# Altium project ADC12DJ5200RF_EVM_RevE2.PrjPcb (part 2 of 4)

## Sheet Clocks2_RevE2.SchDoc: EVM REF CLK
size 431 x 279 mm; Date: Not shown in title block; ApprovedBy: Not shown in title block; CheckedBy: Not shown in title block; Author: Not shown in title block; CompanyName: Not shown in title block; DrawnBy: DWG; Engineer: DWG; Organization: Not shown in title block; Address1: Not shown in title block; Address2: Not shown in title block; Address3: Not shown in title block; Address4: Not shown in title block; DocumentNumber: 6; Revision: Use project parameter SCH_Rev; SheetNumber: 6; SheetTotal: 15; PageSetup: Record=PageOptions¦CenterHorizontal=True¦CenterVertical=True¦PrintScale=1.00¦XCorrection=1.00¦YCorrection=1.00¦PrintKind=0¦BorderSize=5000000¦LeftOffset=0¦BottomOffset=0¦Orientation=2¦PaperLength=1000¦PaperWidth=1000¦Scale=100¦PaperSource=15¦PrintQuality=600¦MediaType=1¦DitherType=10¦PaperKind=Letter¦PrintScaleMode=1
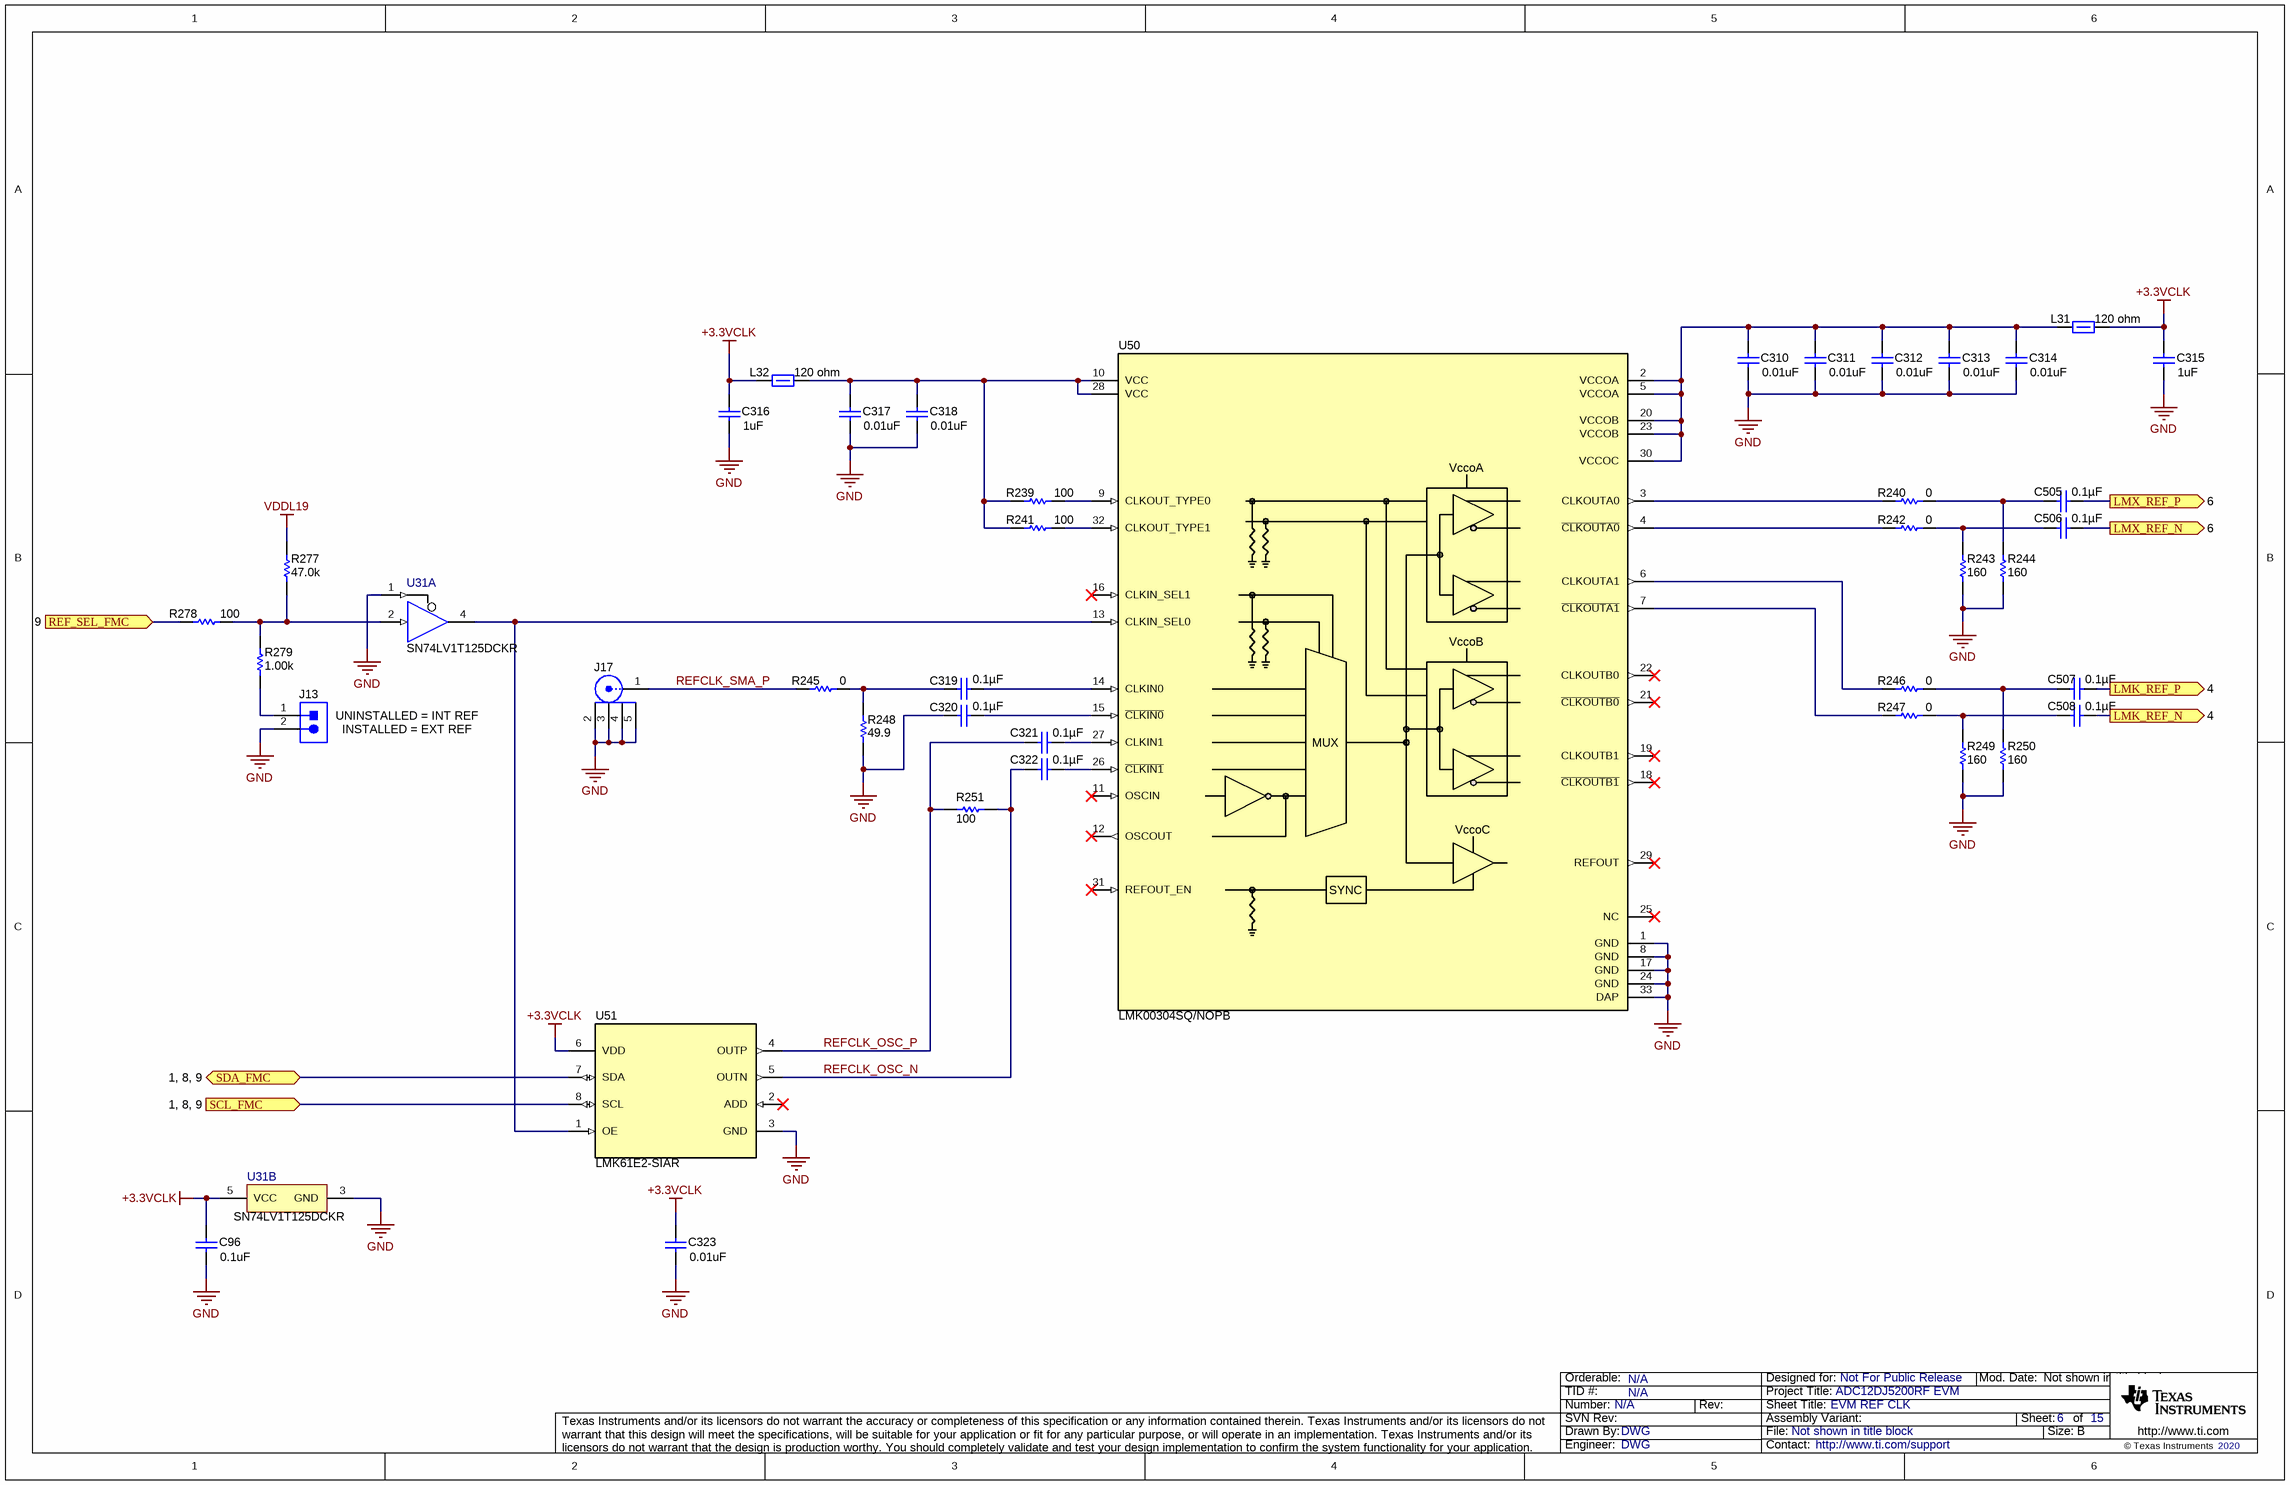
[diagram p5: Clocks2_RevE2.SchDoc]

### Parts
C96  ValueDisplayed: 0.1uF  [0201L]  (hidden comment: GRM033Z71C104KE14D)
C310  ValueDisplayed: 0.01uF  [0201L]  (hidden comment: GRM033R71A103KA01D)
C311  ValueDisplayed: 0.01uF  [0201L]  (hidden comment: GRM033R71A103KA01D)
C312  ValueDisplayed: 0.01uF  [0201L]  (hidden comment: GRM033R71A103KA01D)
C313  ValueDisplayed: 0.01uF  [0201L]  (hidden comment: GRM033R71A103KA01D)
C314  ValueDisplayed: 0.01uF  [0201L]  (hidden comment: GRM033R71A103KA01D)
C315  ValueDisplayed: 1uF  [0402L]  (hidden comment: GRM155R70J105KA12D)
C316  ValueDisplayed: 1uF  [0402L]  (hidden comment: GRM155R70J105KA12D)
C317  ValueDisplayed: 0.01uF  [0201L]  (hidden comment: GRM033R71A103KA01D)
C318  ValueDisplayed: 0.01uF  [0201L]  (hidden comment: GRM033R71A103KA01D)
C319  ValueDisplayed: 0.1µF  [0201_033L]  (hidden comment: 0201BB104KW160)
C320  ValueDisplayed: 0.1µF  [0201_033L]  (hidden comment: 0201BB104KW160)
C321  ValueDisplayed: 0.1µF  [0201_033L]  (hidden comment: 0201BB104KW160)
C322  ValueDisplayed: 0.1µF  [0201_033L]  (hidden comment: 0201BB104KW160)
C323  ValueDisplayed: 0.01uF  [0201L]  (hidden comment: GRM033R71A103KA01D)
C505  ValueDisplayed: 0.1µF  [0201_033L]  (hidden comment: 0201BB104KW160)
C506  ValueDisplayed: 0.1µF  [0201_033L]  (hidden comment: 0201BB104KW160)
C507  ValueDisplayed: 0.1µF  [0201_033L]  (hidden comment: 0201BB104KW160)
C508  ValueDisplayed: 0.1µF  [0201_033L]  (hidden comment: 0201BB104KW160)
J13  5-146261-1  [CONN_5-146261-1]  (value not drawn)
J17  SASF546-P26-X1  [CONN_LTI_SASF546-P26-X1]  (value not drawn)
L31  ValueDisplayed: 120 ohm  [0402L]  (hidden comment: 74279271)
L32  ValueDisplayed: 120 ohm  [0402L]  (hidden comment: 74279271)
R239  ValueDisplayed: 100  [0201L]  (hidden comment: RC0201FS-7D100RL)
R240  ValueDisplayed: 0  [0201L]  (hidden comment: CRCW02010000Z0ED)
R241  ValueDisplayed: 100  [0201L]  (hidden comment: RC0201FS-7D100RL)
R242  ValueDisplayed: 0  [0201L]  (hidden comment: CRCW02010000Z0ED)
R243  ValueDisplayed: 160  [0201L]  (hidden comment: RC0201FR-07160RL)
R244  ValueDisplayed: 160  [0201L]  (hidden comment: RC0201FR-07160RL)
R245  ValueDisplayed: 0  [0201L]  (hidden comment: CRCW02010000Z0ED)
R246  ValueDisplayed: 0  [0201L]  (hidden comment: CRCW02010000Z0ED)
R247  ValueDisplayed: 0  [0201L]  (hidden comment: CRCW02010000Z0ED)
R248  ValueDisplayed: 49.9  [0402L]  (hidden comment: ERJ-2RKF49R9X)
R249  ValueDisplayed: 160  [0201L]  (hidden comment: RC0201FR-07160RL)
R250  ValueDisplayed: 160  [0201L]  (hidden comment: RC0201FR-07160RL)
R251  ValueDisplayed: 100  [0201L]  (hidden comment: RC0201FS-7D100RL)
R277  ValueDisplayed: 47.0k  [0201L]  (hidden comment: RC0201FR-7D47KL)
R278  ValueDisplayed: 100  [0201L]  (hidden comment: RC0201FS-7D100RL)
R279  ValueDisplayed: 1.00k  [0201L]  (hidden comment: RC0201FS-7D1KL)
U31  SN74LV1T125DCKR  [DCK0005A_N]  (parts A,B of 2)
U50  LMK00304SQ/NOPB  [RTV0032A]
U51  LMK61E2-SIAR  [SIA0008B]

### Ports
LMK_REF_N (out, see 4), LMK_REF_P (out, see 4), LMX_REF_N (out, see 6), LMX_REF_P (out, see 6), REF_SEL_FMC (in, see 9), SCL_FMC (in, see 1, 8, 9), SDA_FMC (bidir, see 1, 8, 9)

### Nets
+3.3VCLK: C96.1 C315.1 C316.1 C323.1 L31.2 L32.1 U31.5(VCC) U51.6(VDD)
GND: C96.2 C310.2 C311.2 C312.2 C313.2 C314.2 C315.2 C316.2 C317.2 C318.2 C320.2 C323.2 J13.2 J17.2 J17.3 J17.4 J17.5 R243.1 R244.1 R248.1 R249.1 R250.1 U31.1(~{OE}) U31.3(GND) U50.1(GND) U50.8(GND) U50.17(GND) U50.24(GND) U50.33(DAP) U51.3(GND)
VDDL19: R277.2
LMK_REF_N: C508.1 ; port LMK_REF_N
LMK_REF_P: C507.1 ; port LMK_REF_P
LMX_REF_N: C506.1 ; port LMX_REF_N
LMX_REF_P: C505.1 ; port LMX_REF_P
REF_SEL_FMC: R278.2 ; port REF_SEL_FMC
REFCLK_OSC_N: C322.2 R251.1 U51.5(OUTN)
REFCLK_OSC_P: C321.2 R251.2 U51.4(OUTP)
REFCLK_SMA_P: J17.1 R245.1
SCL_FMC: U51.8(SCL) ; port SCL_FMC
SDA_FMC: U51.7(SDA) ; port SDA_FMC
NetC310_1: C310.1 C311.1 C312.1 C313.1 C314.1 L31.1 U50.2(VCCOA) U50.5(VCCOA) U50.20(VCCOB) U50.23(VCCOB) U50.30(VCCOC)
NetC317_1: C317.1 C318.1 L32.2 R239.2 R241.2 U50.10(VCC) U50.28(VCC)
NetC319_1: C319.1 U50.14(CLKIN0)
NetC319_2: C319.2 R245.2 R248.2
NetC320_1: C320.1 U50.15(~{CLKIN0})
NetC321_1: C321.1 U50.27(CLKIN1)
NetC322_1: C322.1 U50.26(~{CLKIN1})
NetC505_2: C505.2 R240.2 R244.2
NetC506_2: C506.2 R242.2 R243.2
NetC507_2: C507.2 R246.2 R250.2
NetC508_2: C508.2 R247.2 R249.2
NetJ13_1: J13.1 R279.1
NetR239_1: R239.1 U50.9(CLKOUT_TYPE0)
NetR240_1: R240.1 U50.3(CLKOUTA0)
NetR241_1: R241.1 U50.32(CLKOUT_TYPE1)
NetR242_1: R242.1 U50.4(~{CLKOUTA0})
NetR246_1: R246.1 U50.6(CLKOUTA1)
NetR247_1: R247.1 U50.7(~{CLKOUTA1})
NetR277_1: R277.1 R278.1 R279.2 U31.2(A)
NetU31_4: U31.4(Y) U50.13(CLKIN_SEL0) U51.1(OE)

Not connected (* = marked no-connect by the designer): U50 11(OSCIN)* 12(OSCOUT)* 16(CLKIN_SEL1)* 18(~{CLKOUTB1})* 19(CLKOUTB1)* 21(~{CLKOUTB0})* 22(CLKOUTB0)* 25(NC)* 29(REFOUT)* 31(REFOUT_EN)*; U51 2(ADD)*

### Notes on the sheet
- (near J13) UNINSTALLED = INT REF
- (near J13) INSTALLED = EXT REF

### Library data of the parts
C96 = CMP-0064970-1: CAP, CERM, 0.1 uF, 16 V,+/- 10%, X7R, 0201; Manufacturer: MuRata; TaMin_C: -55°C; Polarized: N; SizeAreaWB_mm2: 2.08; Value1: Unknown; U/M: EA; Value: 0.1uF; TaMax_C: 125°C; SizeZ_mm: 0.26; SizeX_mm: 0.6; SizeY_mm: 0.3; Cap_Case: 0201; Value2: 16V; SizeArea_mm2: 0.18; CompType: Capacitor; Cap_F: 100nF; AEC Category: Q200
C310-C314 C317 C318 C323 = CMP-0009732-1: CAP, CERM, 0.01 uF, 10 V, +/- 10%, X7R, 0201; Manufacturer: MuRata; TaMin_C: -55°C; Polarized: N; SizeAreaWB_mm2: 2.08; Value1: Unknown; U/M: EA; Value: 0.01uF; TaMax_C: 125°C; SizeZ_mm: 0.26; SizeX_mm: 0.6; SizeY_mm: 0.3; Cap_Case: 0201; Value2: 10V; SizeArea_mm2: 0.18; CompType: Capacitor; Cap_F: 10nF; AEC Category: Q200
C315 C316 = CMP-0064947-2: CAP, CERM, 1 uF, 6.3 V,+/- 10%, X7R, 0402; Manufacturer: MuRata; TaMin_C: -55°C; Polarized: N; SizeAreaWB_mm2: 3; Value1: Unknown; U/M: EA; Value: 1uF; TaMax_C: 125°C; SizeZ_mm: 0.6; SizeX_mm: 1; SizeY_mm: 0.5; Cap_Case: 0402; Value2: 6.3V; CompType: Capacitor; Cap_F: 1µF; AEC Category: Q200
C319-C322 C505-C508 = CMP-0860981-1: CAP, CERM, 0.1 µF, 16 V,+/- 10%, X7R, 0201; Manufacturer: Passive Plus; Cap_F: 100nF; SizeAreaWB_mm2: 2.08; SizeArea_mm2: 0.18; AEC Qualified: N; AEC Category: Q200; Value: 0.1uF; TaMax_C: 125°C; SizeZ_mm: 0.33; TaMin_C: -55°C; VDC_V: 16V; SizeY_mm: 0.3; U/M: EA; SizeX_mm: 0.6; Cap_Case: 0201
J13 = CMP-0054947-1: Header, 100mil, 2x1, Gold, TH; Manufacturer: TE Connectivity; CT: FALSE; Green_REACh: Passed; CNHeader: TRUE; Green_Lifecycle: Active
J17 = CMP-0055826-1: Connector, SMA,Vertical, Thru hole w/SMT center pin; Manufacturer: Lighthorse Technologies; CT: TRUE; Green_REACh: Incomplete; CNHeader: FALSE; Green_Lifecycle: Not Set
L31 L32 = CMP-0003214-1: Ferrite Bead, 120 ohm @ 100 MHz, 0.5 A, 0402; Manufacturer: Wurth Elektronik; Ztyp@1GHz_Ohm: 175.42; ZTyp@100MHz_Ohm: 120; SizeAreaWB_mm2: 3; DCR_ohm: 2d; Value1: 0.2 ohm; Value: 120 ohm; Imax_A: 5dA; SizeZ_mm: 0.6; SizeX_mm: 1; SizeY_mm: 0.5; Value2: 0.5A
R239 R241 R251 R278 = CMP-0028070-1: RES, 100, 1%, 0.05 W, 0201; Manufacturer: Yageo America; Power_W: 50mW; TempCo: 200 ppm/C; Value_Code: 100R; U/M: EA; Value: 100; EIA_Code: E96; SizeX_mm: 0.6; SizeY_mm: 0.3; SizeZ_mm: 0.26; Value2: 0.05W; SizeArea_mm2: 0.18; CompType: Resistor; AEC Qualified: N; VDC_V: 25V; AEC Category: Q200
R240 R242 R245-R247 = CMP-0027008-4: RES, 0, 5%, 0.05 W, 0201; Manufacturer: Vishay-Dale; Power_W: 50mW; TempCo: ppm/C; Value_Code: 0000; Value: 0; EIA_Code: E24; SizeX_mm: 0.6; SizeY_mm: 0.3; SizeZ_mm: 0.26; Value2: 0.05W; SizeArea_mm2: 0.18; CompType: Resistor; AEC Qualified: N; AEC Category: Q200
R243 R244 R250 = CMP-0027379-2: RES, 160, 1%, 0.05 W, 0201; Manufacturer: Yageo America; Power_W: 50mW; TempCo: 200 ppm/C; Value_Code: 160R; U/M: EA; Value: 160; SizeX_mm: 0.6; SizeY_mm: 0.3; SizeZ_mm: 0.26; Value2: 0.05W; SizeArea_mm2: 0.18; AEC Qualified: N; VDC_V: 25V; AEC Category: Q200
R248 = CMP-0026703-1: RES, 49.9, 1%, 0.1 W, AEC-Q200 Grade 0, 0402; Manufacturer: Panasonic; Power_W: 100mW; TempCo: 100 ppm/C; Value_Code: 49R9; U/M: EA; Value: 49.9; EIA_Code: E96; SizeX_mm: 1; SizeY_mm: 0.5; SizeZ_mm: 0.6; Value2: 0.1W; CompType: Resistor; AEC Qualified: Y; VDC_V: 50V; AEC Grade: 0; AEC Category: Q200
R249 = CMP-0027379-2: RES, 160, 1%, 0.05 W, 0201; Manufacturer: Yageo America; Power_W: 50mW; TempCo: 200 ppm/C; Value_Code: 160R; U/M: EA; Value: 160; SizeX_mm: 0.6; SizeY_mm: 0.3; SizeZ_mm: 0.26; Value2: 0.05W; SizeArea_mm2: 0.18; CompType: Resistor; AEC Qualified: N; VDC_V: 25V; AEC Category: Q200
R277 = CMP-0028024-1: RES, 47.0 k, 1%, 0.05 W, 0201; Manufacturer: Yageo America; Power_W: 50mW; TempCo: 200 ppm/C; Value_Code: 47k0; U/M: EA; Value: 47.0k; Res_ohm: 47k; SizeX_mm: 0.6; SizeY_mm: 0.3; SizeZ_mm: 0.26; Value2: 0.05W; SizeArea_mm2: 0.18; CompType: Resistor; AEC Qualified: N; VDC_V: 25V; AEC Category: Q200
R279 = CMP-0028084-1: RES, 1.00 k, 1%, 0.05 W, 0201; Manufacturer: Yageo America; Power_W: 50mW; TempCo: 200 ppm/C; Value_Code: 1k00; U/M: EA; Value: 1.00k; EIA_Code: E96; Res_ohm: 1k; SizeX_mm: 0.6; SizeY_mm: 0.3; SizeZ_mm: 0.26; Value2: 0.05W; SizeArea_mm2: 0.18; CompType: Resistor; AEC Qualified: N; VDC_V: 25V; AEC Category: Q200
U31 = CMP-0051325-2: Single Power Supply, Single BUFFER GATE w/ 3-State Output (active low enable), DCK0005A, LARGE T&R; Manufacturer: Texas Instruments; tpd @ Nom Voltage(Max)(ns): 14.5,9.5,8.0,6.5; Output Drive (IOL/IOH)(Max)(mA): 8/-8; Voltage(Nom)(V): 1.8,2.5,3.3,5.5; Bits(#): 1; Rating: Catalog; Output Type: CMOS; Technology Family: LV1T; 3-State Output: Yes; Sub-Family: Non-Inverting Buffer/Driver; Logic: True; Input Type: TTL; Schmitt Trigger: No; VCC(Min)(V): 1.6; Special Features: 1.8V to 3.3V Up Translation,3.3V to 1.8V Down Translation,5V Input Tolerant; VCC(Max)(V): 5.5; ICC @ Nom Voltage(Max)(mA): 0.01; F @ Nom Voltage(Max)(Mhz): 50; AEC Category: Q200; AEC Qualified: N; CompType: IC; SizeAreaWB_mm2: 9.3; SizeArea_mm2: 4.2; SizeX_mm: 2.1; SizeY_mm: 2.0; SizeZ_mm: 1.1
U50 = CMP-0065665-2: 3.1-GHz Differential Clock Buffer/Level Translator, RTV0032A (WQFN-32); Alternate Manufacturer: Texas Instruments; Green_Lifecycle: Active; SizeAreaWB_mm2: 49.0; Green_REACh: Passed; SizeZ_mm: 0.8; SizeX_mm: 5.0; SizeArea_mm2: 25.0; CompType: IC; AEC Category: Q200; AEC Qualified: N
U51 = CMP-0075884-1: Ultra-Low Jitter Fully Programmable Oscillator, Integrated EEPROM, +/-50ppm, SIA0008B (QFM-8); Manufacturer: Texas Instruments; Alternate PartNumber: LMK61E2-SIAT; SizeAreaWB_mm2: 20.25; SizeArea_mm2: 12.25; SizeZ_mm: 2.0; SizeY_mm: 3.5; U/M: EA; CompType: IC

## Sheet Clocks3_RevE2.SchDoc: EVM LMX
size 431 x 279 mm; Date: Not shown in title block; ApprovedBy: Not shown in title block; CheckedBy: Not shown in title block; Author: Not shown in title block; CompanyName: Not shown in title block; DrawnBy: DWG; Engineer: DWG; Organization: Not shown in title block; Address1: Not shown in title block; Address2: Not shown in title block; Address3: Not shown in title block; Address4: Not shown in title block; DocumentNumber: 7; Revision: Use project parameter SCH_Rev; SheetNumber: 7; SheetTotal: 15; PageSetup: Record=PageOptions¦CenterHorizontal=True¦CenterVertical=True¦PrintScale=1.00¦XCorrection=1.00¦YCorrection=1.00¦PrintKind=0¦BorderSize=5000000¦LeftOffset=0¦BottomOffset=0¦Orientation=2¦PaperLength=1000¦PaperWidth=1000¦Scale=100¦PaperSource=15¦PrintQuality=600¦MediaType=1¦DitherType=10¦PaperKind=Letter¦PrintScaleMode=1
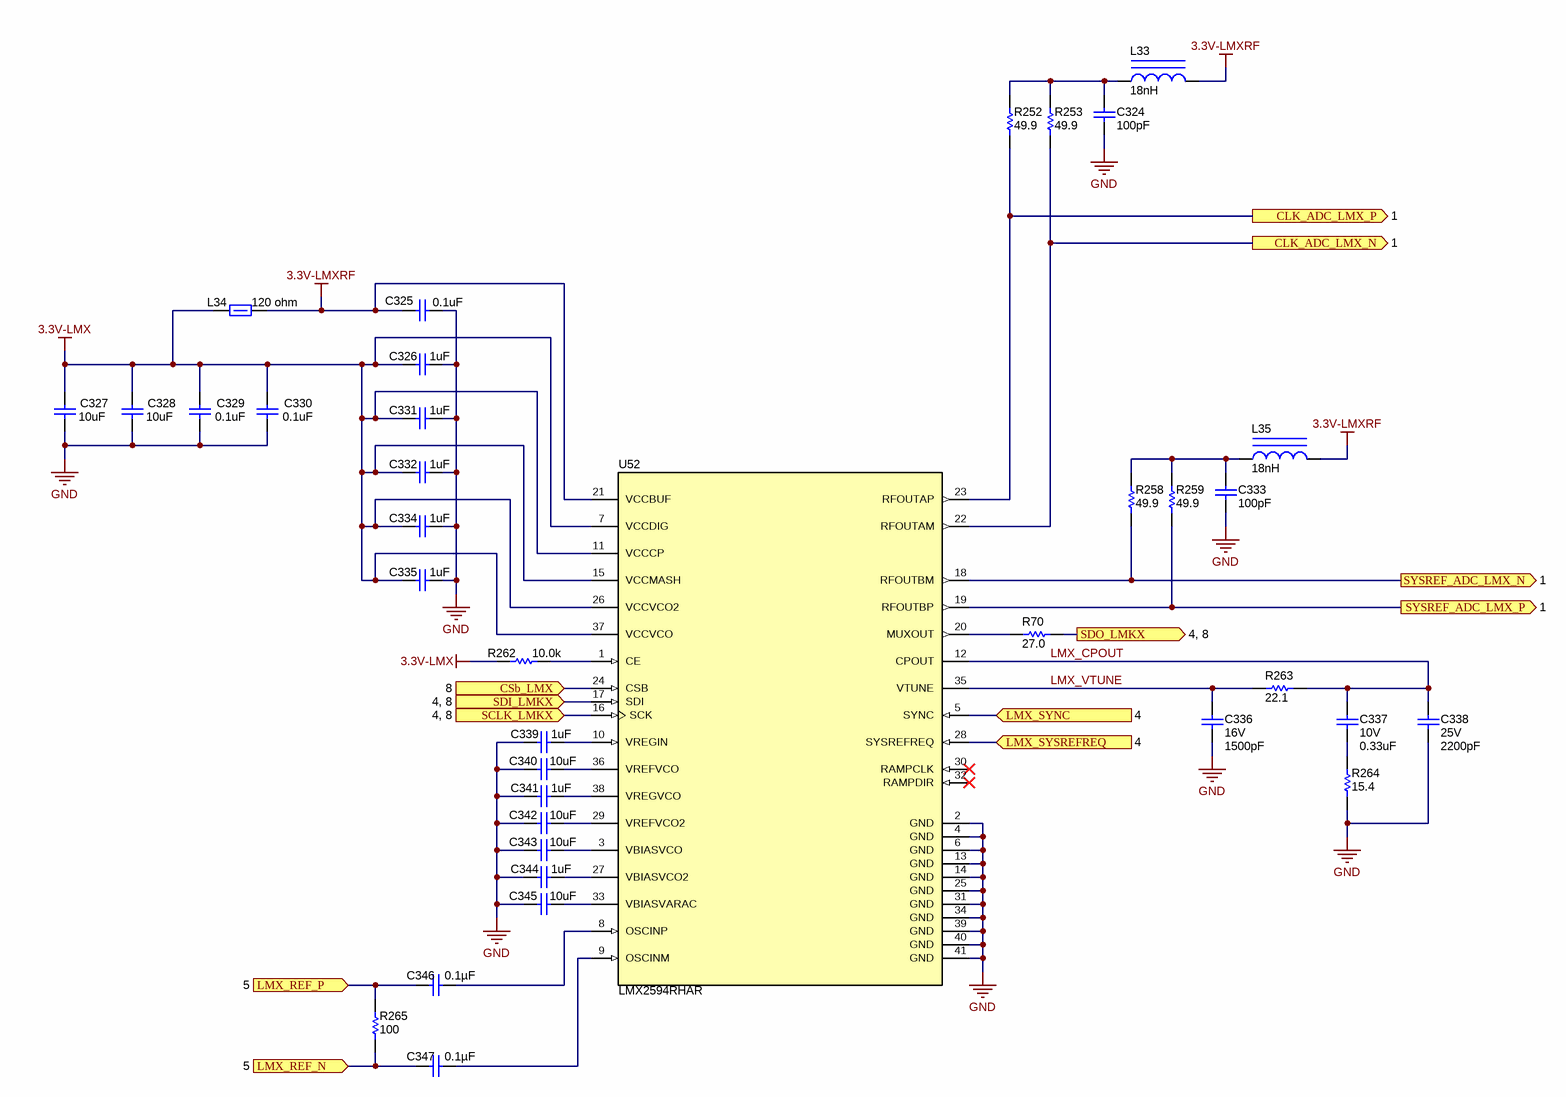
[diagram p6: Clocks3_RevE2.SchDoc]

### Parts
C324  ValueDisplayed: 100pF  [0201_033]  (hidden comment: C0603C0G1E101J030BA)
C325  ValueDisplayed: 0.1uF  [0201L]  (hidden comment: GRM033Z71C104KE14D)
C326  ValueDisplayed: 1uF  [0402L]  (hidden comment: GRM155R70J105KA12D)
C327  ValueDisplayed: 10uF  [0603]  (hidden comment: GRM188Z71A106MA73D)
C328  ValueDisplayed: 10uF  [0603]  (hidden comment: GRM188Z71A106MA73D)
C329  ValueDisplayed: 0.1uF  [0201L]  (hidden comment: GRM033Z71C104KE14D)
C330  ValueDisplayed: 0.1uF  [0201L]  (hidden comment: GRM033Z71C104KE14D)
C331  ValueDisplayed: 1uF  [0402L]  (hidden comment: GRM155R70J105KA12D)
C332  ValueDisplayed: 1uF  [0402L]  (hidden comment: GRM155R70J105KA12D)
C333  ValueDisplayed: 100pF  [0201_033]  (hidden comment: C0603C0G1E101J030BA)
C334  ValueDisplayed: 1uF  [0402L]  (hidden comment: GRM155R70J105KA12D)
C335  ValueDisplayed: 1uF  [0402L]  (hidden comment: GRM155R70J105KA12D)
C336  VDC_V: 16V  ValueDisplayed: 1500pF  [0201]  (hidden comment: GRM033R71C182KA88D)
C337  VDC_V: 10V  ValueDisplayed: 0.33uF  [0402L]  (hidden comment: GRM155R71C563KA88D)
C338  VDC_V: 25V  ValueDisplayed: 2200pF  [0201_033]  (hidden comment: CGA1A2X7R1E152K030BA)
C339  ValueDisplayed: 1uF  [0402L]  (hidden comment: GRM155R70J105KA12D)
C340  ValueDisplayed: 10uF  [0603]  (hidden comment: GRM188Z71A106MA73D)
C341  ValueDisplayed: 1uF  [0402L]  (hidden comment: GRM155R70J105KA12D)
C342  ValueDisplayed: 10uF  [0603]  (hidden comment: GRM188Z71A106MA73D)
C343  ValueDisplayed: 10uF  [0603]  (hidden comment: GRM188Z71A106MA73D)
C344  ValueDisplayed: 1uF  [0402L]  (hidden comment: GRM155R70J105KA12D)
C345  ValueDisplayed: 10uF  [0603]  (hidden comment: GRM188Z71A106MA73D)
C346  ValueDisplayed: 0.1µF  [0201_033L]  (hidden comment: 0201BB104KW160)
C347  ValueDisplayed: 0.1µF  [0201_033L]  (hidden comment: 0201BB104KW160)
L33  ValueDisplayed: 18nH  [IND_LQG15H]  (hidden comment: LQG15HS18NJ02D)
L34  ValueDisplayed: 120 ohm  [0402]  (hidden comment: 74279271)
L35  ValueDisplayed: 18nH  [IND_LQG15H]  (hidden comment: LQG15HS18NJ02D)
R70  ValueDisplayed: 27.0  [0201]  (hidden comment: CRCW02010000Z0ED)
R252  ValueDisplayed: 49.9  [0402L]  (hidden comment: CRCW040249R9FKED)
R253  ValueDisplayed: 49.9  [0402L]  (hidden comment: CRCW040249R9FKED)
R258  ValueDisplayed: 49.9  [0402L]  (hidden comment: CRCW040249R9FKED)
R259  ValueDisplayed: 49.9  [0402L]  (hidden comment: CRCW040249R9FKED)
R262  ValueDisplayed: 10.0k  [0201]  (hidden comment: RC0201FR-7D10KL)
R263  ValueDisplayed: 22.1  [0201]  (hidden comment: RC0201FR-7D270RL)
R264  ValueDisplayed: 15.4  [0201]  (hidden comment: RC0201FR-7D120RL)
R265  ValueDisplayed: 100  [0201L]  (hidden comment: RC0201FS-7D100RL)
U52  LMX2594RHAR  [RHA0040H]

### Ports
CLK_ADC_LMX_N (out, see 1), CLK_ADC_LMX_P (out, see 1), CSb_LMX (in, see 8), LMX_REF_N (in, see 5), LMX_REF_P (in, see 5), LMX_SYNC (in, see 4), LMX_SYSREFREQ (in, see 4), SCLK_LMKX (in, see 4, 8), SDI_LMKX (in, see 4, 8), SDO_LMKX (out, see 4, 8), SYSREF_ADC_LMX_N (out, see 1), SYSREF_ADC_LMX_P (out, see 1)

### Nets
3.3V-LMX: C326.1 C327.2 C328.2 C329.2 C330.2 C331.1 C332.1 C334.1 C335.1 L34.1 R262.2 U52.7(VCCDIG) U52.11(VCCCP) U52.15(VCCMASH) U52.26(VCCVCO2) U52.37(VCCVCO)
3.3V-LMXRF: C325.1 L33.2 L34.2 L35.2 U52.21(VCCBUF)
GND: C324.2 C325.2 C326.2 C327.1 C328.1 C329.1 C330.1 C331.2 C332.2 C333.2 C334.2 C335.2 C336.2 C338.2 C339.1 C340.1 C341.1 C342.1 C343.1 C344.1 C345.1 R264.1 U52.2(GND) U52.4(GND) U52.6(GND) U52.13(GND) U52.14(GND) U52.25(GND) U52.31(GND) U52.34(GND) U52.39(GND) U52.40(GND) U52.41(GND)
CLK_ADC_LMX_N: R253.1 U52.22(RFOUTAM) ; port CLK_ADC_LMX_N
CLK_ADC_LMX_P: R252.1 U52.23(RFOUTAP) ; port CLK_ADC_LMX_P
CSb_LMX: U52.24(CSB) ; port CSb_LMX
LMX_CPOUT: C337.1 C338.1 R263.2 U52.12(CPOUT)
LMX_REF_N: C347.2 R265.1 ; port LMX_REF_N
LMX_REF_P: C346.2 R265.2 ; port LMX_REF_P
LMX_SYNC: U52.5(SYNC) ; port LMX_SYNC
LMX_SYSREFREQ: U52.28(SYSREFREQ) ; port LMX_SYSREFREQ
LMX_VTUNE: C336.1 R263.1 U52.35(VTUNE)
SCLK_LMKX: U52.16(SCK) ; port SCLK_LMKX
SDI_LMKX: U52.17(SDI) ; port SDI_LMKX
SDO_LMKX: R70.1 ; port SDO_LMKX
SYSREF_ADC_LMX_N: R258.1 U52.18(RFOUTBM) ; port SYSREF_ADC_LMX_N
SYSREF_ADC_LMX_P: R259.1 U52.19(RFOUTBP) ; port SYSREF_ADC_LMX_P
NetC324_1: C324.1 L33.1 R252.2 R253.2
NetC333_1: C333.1 L35.1 R258.2 R259.2
NetC337_2: C337.2 R264.2
NetC339_2: C339.2 U52.10(VREGIN)
NetC340_2: C340.2 U52.36(VREFVCO)
NetC341_2: C341.2 U52.38(VREGVCO)
NetC342_2: C342.2 U52.29(VREFVCO2)
NetC343_2: C343.2 U52.3(VBIASVCO)
NetC344_2: C344.2 U52.27(VBIASVCO2)
NetC345_2: C345.2 U52.33(VBIASVARAC)
NetC346_1: C346.1 U52.8(OSCINP)
NetC347_1: C347.1 U52.9(OSCINM)
NetR70_2: R70.2 U52.20(MUXOUT)
NetR262_1: R262.1 U52.1(CE)

Not connected (* = marked no-connect by the designer): U52 30(RAMPCLK)* 32(RAMPDIR)*

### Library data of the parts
C324 C333 = CMP-0009632-3: CAP, CERM, 100 pF, 25 V, +/- 5%, C0G/NP0, 0201; Manufacturer: TDK; TaMin_C: -55°C; Polarized: N; SizeAreaWB_mm2: 2.08; Value1: Unknown; U/M: EA; Value: 100pF; TaMax_C: 125°C; SizeZ_mm: 0.33; SizeX_mm: 0.6; SizeY_mm: 0.3; Cap_Case: 0201; Value2: 25V; SizeArea_mm2: 0.18; CompType: Capacitor; AEC Category: Q200
C325 C329 C330 = CMP-0064970-1: as C96 on sheet Clocks2_RevE2
C326 C331 C332 C334 C335 C339 C341 C344 = CMP-0064947-2: CAP, CERM, 1 uF, 6.3 V,+/- 10%, X7R, 0402; Manufacturer: MuRata; TaMin_C: -55°C; Polarized: N; SizeAreaWB_mm2: 3; Value1: Unknown; U/M: EA; Value: 1uF; TaMax_C: 125°C; SizeZ_mm: 0.6; SizeX_mm: 1; SizeY_mm: 0.5; Cap_Case: 0402; Value2: 6.3V; Cap_F: 1µF; AEC Category: Q200
C327 C328 C340 C342 C343 C345 = CMP-0007497-5: CAP, CERM, 10 uF, 10 V, +/- 20%, X7R, 0603; Manufacturer: MuRata; TaMin_C: -55°C; Polarized: N; SizeAreaWB_mm2: 4.68; Value1: Unknown; U/M: EA; Value: 10uF; TaMax_C: 125°C; SizeZ_mm: 1; SizeX_mm: 1.6; SizeY_mm: 0.8; Value2: 10V; SizeArea_mm2: 1.28; CompType: Capacitor; Cap_F: 10µF; AEC Category: Q200
C336 = CMP-0009748-1: CAP, CERM, 1500 pF, 16 V, +/- 10%, X7R, 0201; Manufacturer: MuRata; PartNumber: GRM033R71C152KA01D; TaMin_C: -55°C; Polarized: N; SizeAreaWB_mm2: 2.08; Value1: Unknown; U/M: EA; Value: 1500pF; TaMax_C: 125°C; SizeZ_mm: 0.26; SizeX_mm: 0.6; SizeY_mm: 0.3; SizeArea_mm2: 0.18; Cap_F: 1.5nF; AEC Category: Q200
C337 = CMP-0006264-2: CAP, CERM, 0.33 uF, 10 V, +/- 10%, X5R, 0402; Manufacturer: TDK; PartNumber: C1005X5R1A334K050BB; TaMin_C: -55°C; Polarized: N; SizeAreaWB_mm2: 3; Value1: Unknown; U/M: EA; Value: 0.33uF; TaMax_C: 85°C; SizeZ_mm: 0.6; SizeX_mm: 1; SizeY_mm: 0.5; Cap_Case: 0402; CompType: Capacitor; Cap_F: 330nF; AEC Category: Q200
C338 = CMP-0009647-3: CAP, CERM, 2200 pF, 25 V, +/- 10%, X7R, AEC-Q200 Grade 1, 0201; Manufacturer: TDK; PartNumber: CGA1A2X7R1E222K030BA; TaMin_C: -55°C; ESR_ohm: 1.26834; Polarized: N; SizeAreaWB_mm2: 2.08; Value1: 1.26834 ohm; U/M: EA; Value: 2200pF; TaMax_C: 125°C; SizeZ_mm: 0.33; SizeX_mm: 0.6; SizeY_mm: 0.3; SizeArea_mm2: 0.18; CompType: Capacitor; AEC Qualified: Y; Cap_F: 2.2nF; IRMS_A: 2.01468dA; AEC Grade: 1; AEC Category: Q200
C346 C347 = CMP-0860981-1: as C319-C322 on sheet Clocks2_RevE2
L33 L35 = CMP-0058614-1: Inductor, Multilayer, Air Core, 18 nH, 0.3 A, 0.36 ohm, SMD; Manufacturer: MuRata; Isat: 0.3A @ % inductance drop; Irms: 0.3A @ C rise; Green_Lifecycle: Active; SizeAreaWB_mm2: 3; DCR_ohm: 0.36; Green_REACh: Passed; Value: 18nH; Imax_A: 300mA; SizeZ_mm: 0.55; SizeX_mm: 1; SizeY_mm: 0.5; Value2: 0.3A; AEC Category: Q200
L34 = CMP-0003214-1: as L31 on sheet Clocks2_RevE2
R70 = CMP-0027540-1: RES, 27.0, 1%, 0.05 W, 0201; Manufacturer: Yageo America; PartNumber: RC0201FR-0727RL; Power_W: 50mW; TempCo: 200 ppm/C; Value_Code: 27R0; U/M: EA; Value: 27.0; Res_ohm: 27; SizeX_mm: 0.6; SizeY_mm: 0.3; SizeZ_mm: 0.26; Value2: 0.05W; SizeArea_mm2: 0.18; CompType: Resistor; AEC Qualified: N; VDC_V: 25V; AEC Category: Q200
R252 R253 R258 R259 = CMP-0026404-2: RES, 49.9, 1%, 0.063 W, AEC-Q200 Grade 0, 0402; Manufacturer: Vishay-Dale; Power_W: 63mW; TempCo: 100 ppm/C; Value_Code: 49R9; Value: 49.9; EIA_Code: E96; SizeX_mm: 1; SizeY_mm: 0.5; SizeZ_mm: 0.6; Value2: 0.063W; CompType: Resistor; AEC Qualified: Y; VDC_V: 50V; AEC Category: Q200; AEC Grade: 0
R262 = CMP-0027945-1: RES, 10.0 k, 1%, 0.05 W, 0201; Manufacturer: Yageo America; Power_W: 50mW; TempCo: 200 ppm/C; Value_Code: 10k0; U/M: EA; Value: 10.0k; EIA_Code: E96; Res_ohm: 10k; SizeX_mm: 0.6; SizeY_mm: 0.3; SizeZ_mm: 0.26; Value2: 0.05W; SizeArea_mm2: 0.18; AEC Qualified: N; VDC_V: 25V; AEC Category: Q200
R263 = CMP-0027498-1: RES, 22.1, 1%, 0.05 W, 0201; Manufacturer: Yageo America; PartNumber: RC0201FR-0722R1L; Power_W: 50mW; TempCo: 200 ppm/C; Value_Code: 22R1; U/M: EA; Value: 22.1; EIA_Code: E96; SizeX_mm: 0.6; SizeY_mm: 0.3; SizeZ_mm: 0.26; Value2: 0.05W; SizeArea_mm2: 0.18; AEC Qualified: N; VDC_V: 25V; AEC Category: Q200
R264 = CMP-0027375-2: RES, 15.4, 1%, 0.05 W, 0201; Manufacturer: Yageo America; PartNumber: RC0201FR-0715R4L; Power_W: 50mW; TempCo: 200 ppm/C; Value_Code: 15R4; U/M: EA; Value: 15.4; EIA_Code: E96; SizeX_mm: 0.6; SizeY_mm: 0.3; SizeZ_mm: 0.26; Value2: 0.05W; SizeArea_mm2: 0.18; CompType: Resistor; AEC Qualified: N; VDC_V: 25V; AEC Category: Q200
R265 = CMP-0028070-1: as R239 on sheet Clocks2_RevE2
U52 = CMP-0013786-6: 15 GHz Wideband PLLatinum(TM)RF Synthesizer with Phase Synchronization and JESD204B support, RHA0040H (VQFN-40); Manufacturer: Texas Instruments; Alternate PartNumber: LMX2594RHAT; SizeX_mm: 6; CompType: IC; SizeZ_mm: 1; SizeArea_mm2: 36; SizeAreaWB_mm2: 64; U/M: EA

## Sheet FMC_RevE2.SchDoc: EVM FMC+ Connector
size C; Date: Not shown in title block; ApprovedBy: Not shown in title block; CheckedBy: Not shown in title block; Author: Not shown in title block; CompanyName: Not shown in title block; DrawnBy: DWG; Engineer: DWG; Organization: Not shown in title block; Address1: Not shown in title block; Address2: Not shown in title block; Address3: Not shown in title block; Address4: Not shown in title block; DocumentNumber: 8; Revision: Use project parameter SCH_Rev; SheetNumber: 8; SheetTotal: 15; PageSetup: Record=PageOptions¦CenterHorizontal=True¦CenterVertical=True¦PrintScale=0.64¦XCorrection=1.00¦YCorrection=1.00¦PrintKind=0¦BorderSize=5000000¦LeftOffset=0¦BottomOffset=0¦Orientation=2¦PaperLength=1000¦PaperWidth=1000¦Scale=100¦PaperSource=15¦PrintQuality=600¦MediaType=1¦DitherType=10¦PrintScaleMode=1¦PaperKind=Letter
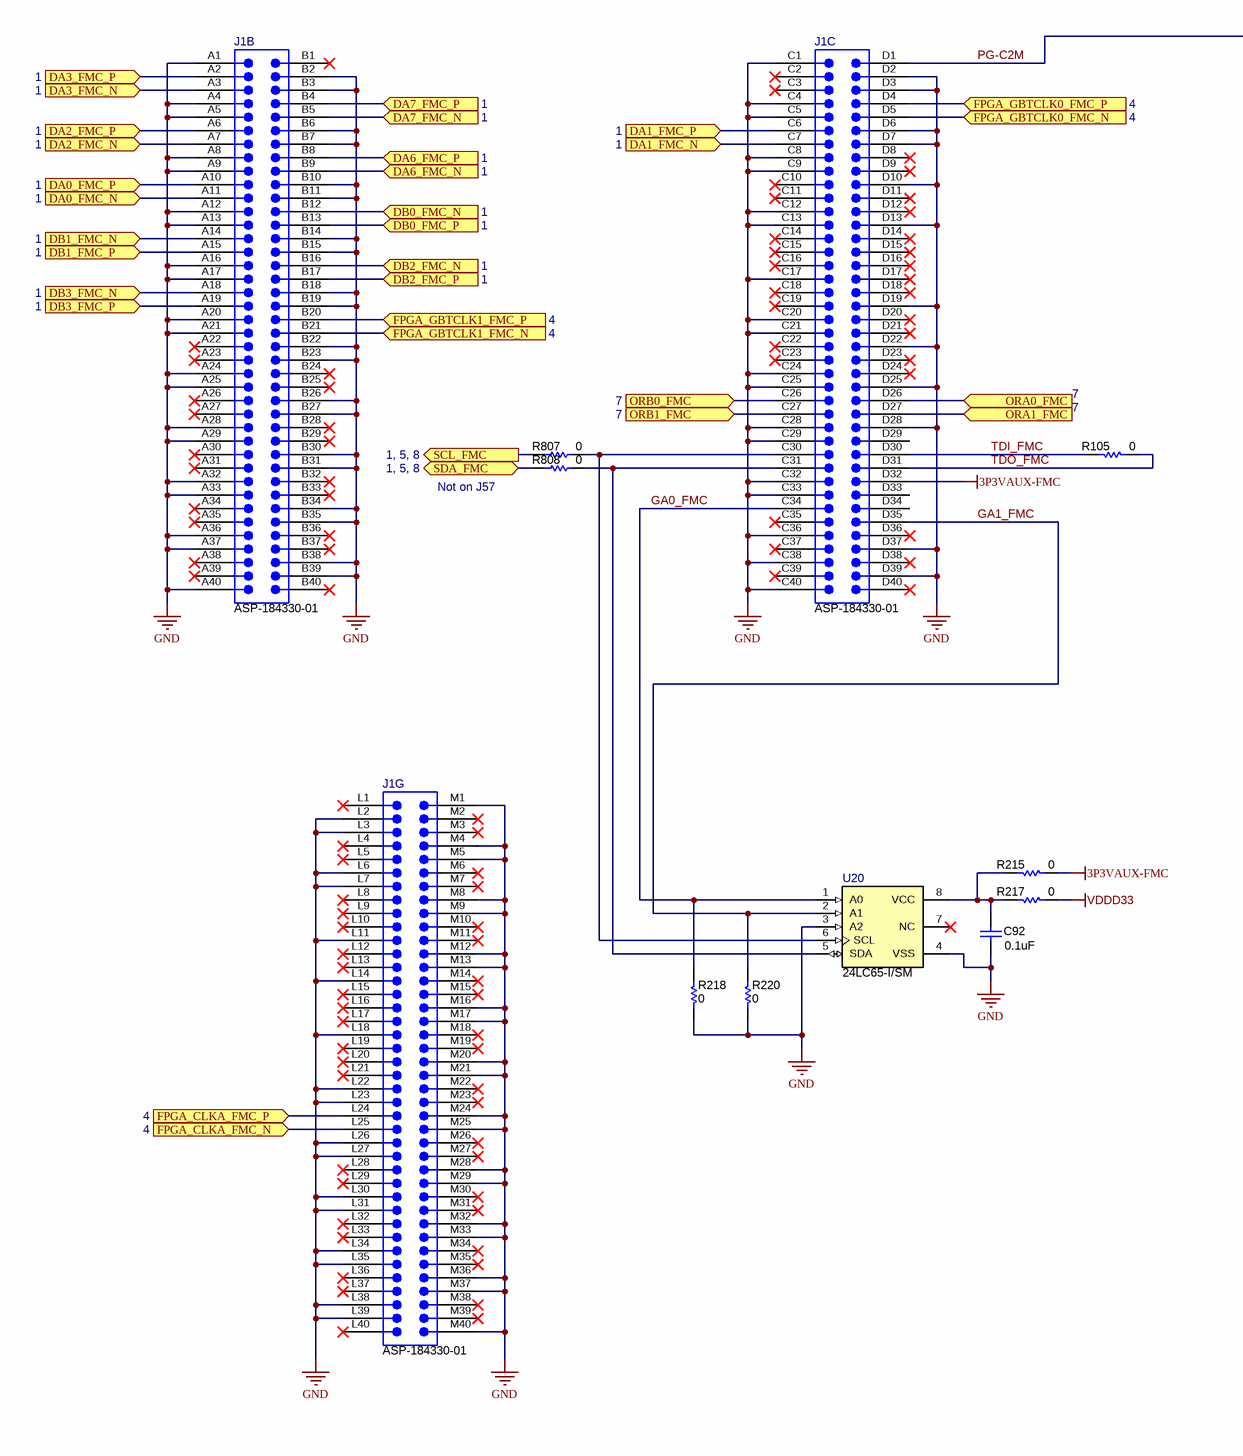
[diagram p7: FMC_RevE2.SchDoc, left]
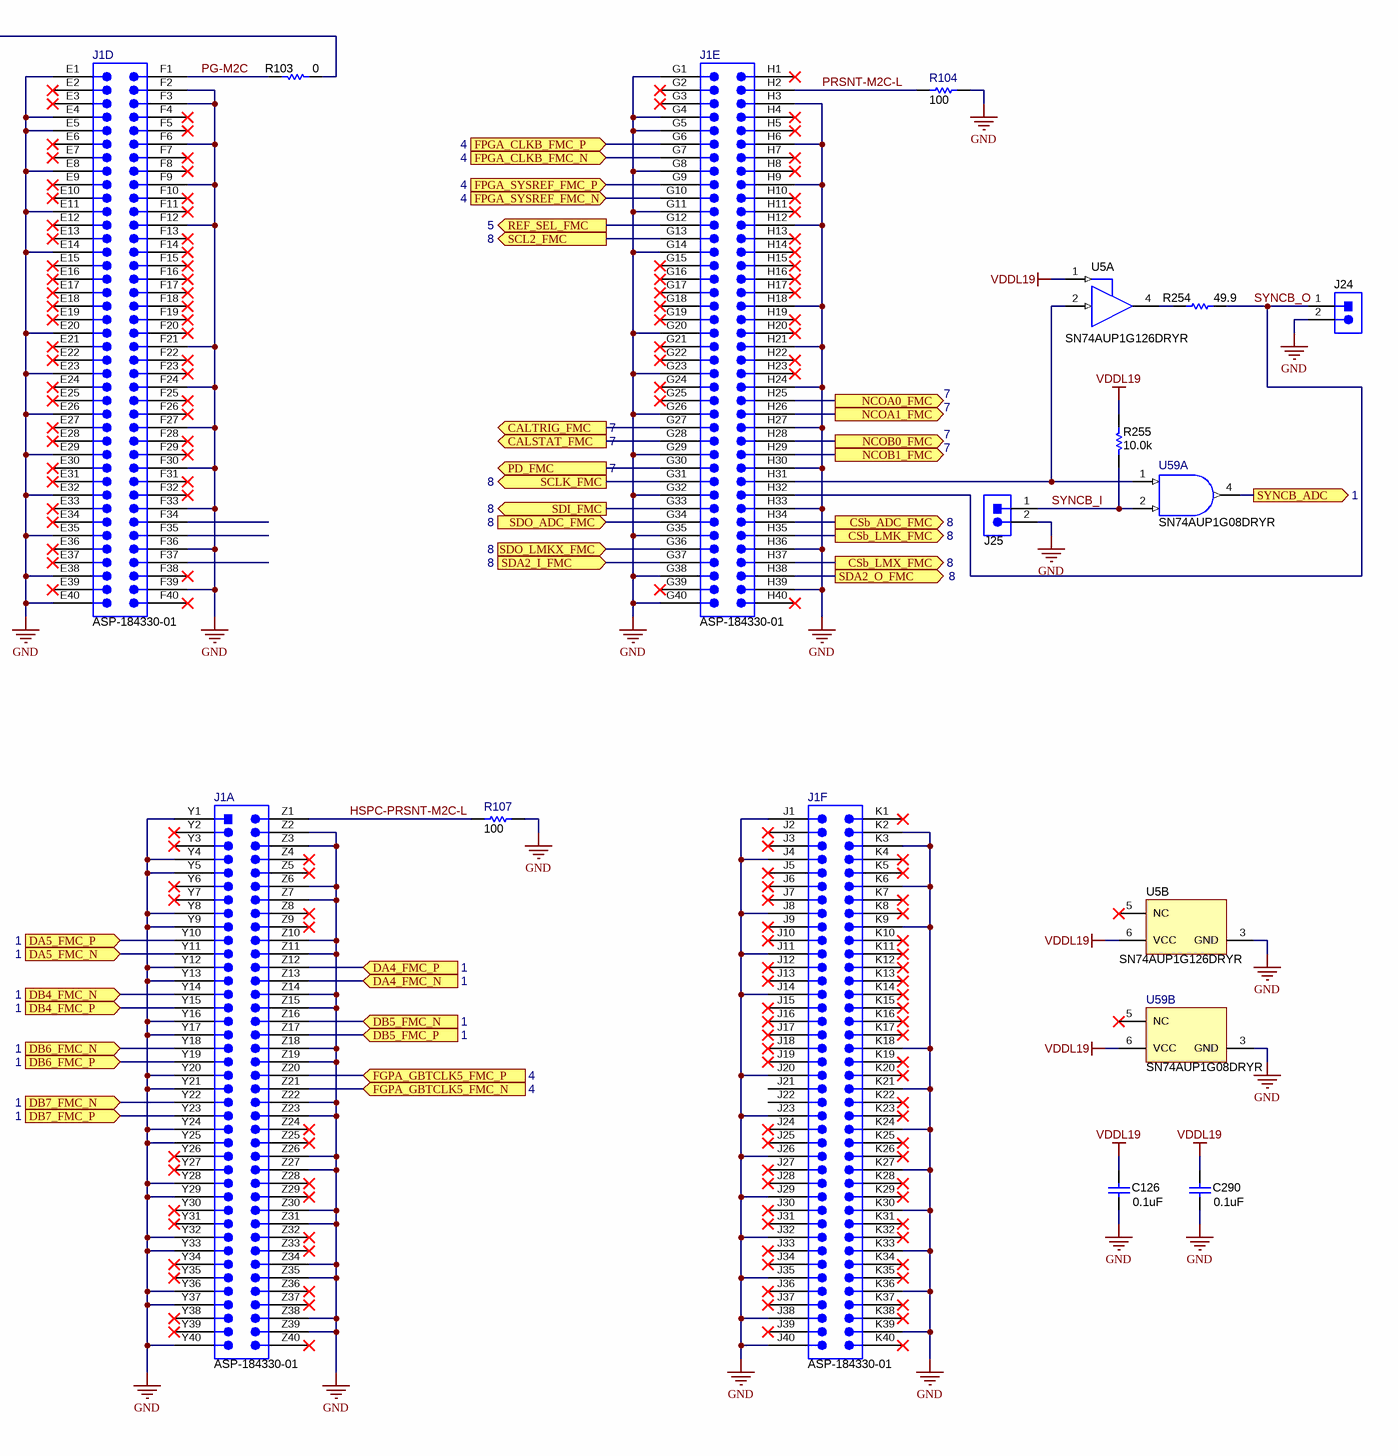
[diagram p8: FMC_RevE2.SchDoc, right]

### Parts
C92  ValueDisplayed: 0.1uF  [0201L]  (hidden comment: GRM033Z71C104KE14D)
C126  ValueDisplayed: 0.1uF  [0201L]  (hidden comment: GRM033Z71C104KE14D)
C290  ValueDisplayed: 0.1uF  [0201L]  (hidden comment: GRM033Z71C104KE14D)
J1  ASP-184330-01  [Samtec_ASP-184330-01]  (parts A,B,C,D,E,F,G of 7)
J24  5-146261-1  [CONN_5-146261-1]  (value not drawn)
J25  5-146261-1  [CONN_5-146261-1]  (value not drawn)
R103  ValueDisplayed: 0  [0201]  (hidden comment: CRCW02010000Z0ED)
R104  ValueDisplayed: 100  [0201]  (hidden comment: RC0201FS-7D100RL)
R105  ValueDisplayed: 0  [0201]  (hidden comment: CRCW02010000Z0ED)
R107  ValueDisplayed: 100  [0201]  (hidden comment: RC0201FS-7D100RL)
R215  ValueDisplayed: 0  [0201L]  (hidden comment: CRCW02010000Z0ED)
R217  ValueDisplayed: 0  [0201L]  (hidden comment: CRCW02010000Z0ED)
R218  ValueDisplayed: 0  [0201L]  (hidden comment: CRCW02010000Z0ED)
R220  ValueDisplayed: 0  [0201L]  (hidden comment: CRCW02010000Z0ED)
R254  ValueDisplayed: 49.9  [0201L]  (hidden comment: RC0201FR-7D49R9L)
R255  ValueDisplayed: 10.0k  [0201L]  (hidden comment: RC0201FR-7D10KL)
R807  ValueDisplayed: 0  [0201L]  (hidden comment: CRCW02010000Z0ED)
R808  ValueDisplayed: 0  [0201L]  (hidden comment: CRCW02010000Z0ED)
U5  SN74AUP1G126DRYR  [DRY0006A]  (parts A,B of 2)
U20  24LC65-I/SM  [SOIC127P800X216-8N]
U59  SN74AUP1G08DRYR  [DRY0006A]  (parts A,B of 2)

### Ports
CALSTAT_FMC (out, see 7), CALTRIG_FMC (out, see 7), CSb_ADC_FMC (out, see 8), CSb_LMK_FMC (out, see 8), CSb_LMX_FMC (out, see 8), DA0_FMC_N (in, see 1), DA0_FMC_P (in, see 1), DA1_FMC_N (in, see 1), DA1_FMC_P (in, see 1), DA2_FMC_N (in, see 1), DA2_FMC_P (in, see 1), DA3_FMC_N (in, see 1), DA3_FMC_P (in, see 1), DA4_FMC_N (in, see 1), DA4_FMC_P (in, see 1), DA5_FMC_N (in, see 1), DA5_FMC_P (in, see 1), DA6_FMC_N (in, see 1), DA6_FMC_P (in, see 1), DA7_FMC_N (in, see 1), DA7_FMC_P (in, see 1), DB0_FMC_N (in, see 1), DB0_FMC_P (in, see 1), DB1_FMC_N (in, see 1), DB1_FMC_P (in, see 1), DB2_FMC_N (in, see 1), DB2_FMC_P (in, see 1), DB3_FMC_N (in, see 1), DB3_FMC_P (in, see 1), DB4_FMC_N (in, see 1), DB4_FMC_P (in, see 1), DB5_FMC_N (in, see 1), DB5_FMC_P (in, see 1), DB6_FMC_N (in, see 1), DB6_FMC_P (in, see 1), DB7_FMC_N (in, see 1), DB7_FMC_P (in, see 1), FGPA_GBTCLK5_FMC_N (in, see 4), FGPA_GBTCLK5_FMC_P (in, see 4), FPGA_CLKA_FMC_N (in, see 4), FPGA_CLKA_FMC_P (in, see 4), FPGA_CLKB_FMC_N (in, see 4), FPGA_CLKB_FMC_P (in, see 4), FPGA_GBTCLK0_FMC_N (in, see 4), FPGA_GBTCLK0_FMC_P (in, see 4), FPGA_GBTCLK1_FMC_N (in, see 4), FPGA_GBTCLK1_FMC_P (in, see 4), FPGA_SYSREF_FMC_N (in, see 4), FPGA_SYSREF_FMC_P (in, see 4), NCOA0_FMC (out, see 7), NCOA1_FMC (out, see 7), NCOB0_FMC (out, see 7), NCOB1_FMC (out, see 7), ORA0_FMC (in, see 7), ORA1_FMC (in, see 7), ORB0_FMC (in, see 7), ORB1_FMC (in, see 7), PD_FMC (out, see 7), REF_SEL_FMC (out, see 5), SCL2_FMC (out, see 8), SCL_FMC (out, see 1, 5, 8), SCLK_FMC (out, see 8), SDA2_I_FMC (in, see 8), SDA2_O_FMC (out, see 8), SDA_FMC (bidir, see 1, 5, 8), SDI_FMC (out, see 8), SDO_ADC_FMC (in, see 8), SDO_LMKX_FMC (in, see 8), SYNCB_ADC (out, see 1)

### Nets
3P3VAUX-FMC: J1.D32 R215.1
GND: C92.2 C126.2 C290.2 J1.A1 J1.A4 J1.A5 J1.A8 J1.A9 J1.A12 J1.A13 J1.A16 J1.A17 J1.A20 J1.A21 J1.A24 J1.A25 J1.A28 J1.A29 J1.A32 J1.A33 J1.A36 J1.A37 J1.A40 J1.B2 J1.B3 J1.B6 J1.B7 J1.B10 J1.B11 J1.B14 J1.B15 J1.B18 J1.B19 J1.B22 J1.B23 J1.B26 J1.B27 J1.B30 J1.B31 J1.B34 J1.B35 J1.B38 J1.B39 J1.C1 J1.C4 J1.C5 J1.C8 J1.C9 J1.C12 J1.C13 J1.C17 J1.C20 J1.C21 J1.C24 J1.C25 J1.C28 J1.C29 J1.C32 J1.C33 J1.C36 J1.C38 J1.C40 J1.D2 J1.D3 J1.D6 J1.D7 J1.D10 J1.D13 J1.D19 J1.D22 J1.D25 J1.D28 J1.D37 J1.D39 J1.E1 J1.E4 J1.E5 J1.E8 J1.E11 J1.E14 J1.E20 J1.E23 J1.E26 J1.E29 J1.E32 J1.E35 J1.E38 J1.E40 J1.F2 J1.F3 J1.F6 J1.F9 J1.F12 J1.F21 J1.F24 J1.F27 J1.F30 J1.F33 J1.F36 J1.F39 J1.G1 J1.G4 J1.G5 J1.G8 J1.G11 J1.G14 J1.G20 J1.G23 J1.G26 J1.G29 J1.G32 J1.G35 J1.G38 J1.G40 J1.H3 J1.H6 J1.H9 J1.H12 J1.H18 J1.H21 J1.H24 J1.H27 J1.H30 J1.H33 J1.H36 J1.H39 J1.J1 J1.J4 J1.J8 J1.J11 J1.J14 J1.J20 J1.J23 J1.J26 J1.J29 J1.J32 J1.J35 J1.J38 J1.J40 J1.K2 J1.K3 J1.K6 J1.K9 J1.K18 J1.K21 J1.K24 J1.K27 J1.K30 J1.K33 J1.K36 J1.K39 J1.L2 J1.L3 J1.L6 J1.L7 J1.L11 J1.L14 J1.L18 J1.L22 J1.L23 J1.L26 J1.L27 J1.L30 J1.L31 J1.L34 J1.L35 J1.L38 J1.L39 J1.M1 J1.M4 J1.M5 J1.M8 J1.M9 J1.M12 J1.M13 J1.M16 J1.M17 J1.M20 J1.M21 J1.M24 J1.M25 J1.M28 J1.M29 J1.M32 J1.M33 J1.M36 J1.M37 J1.M40 J1.Y1 J1.Y4 J1.Y5 J1.Y8 J1.Y9 J1.Y12 J1.Y13 J1.Y16 J1.Y17 J1.Y20 J1.Y21 J1.Y24 J1.Y25 J1.Y28 J1.Y29 J1.Y32 J1.Y33 J1.Y36 J1.Y37 J1.Y40 J1.Z2 J1.Z3 J1.Z6 J1.Z7 J1.Z10 J1.Z11 J1.Z14 J1.Z15 J1.Z18 J1.Z19 J1.Z22 J1.Z23 J1.Z26 J1.Z27 J1.Z30 J1.Z31 J1.Z34 J1.Z35 J1.Z38 J1.Z39 J24.2 J25.2 R104.2 R107.2 R218.2 R220.2 U5.3(GND) U20.3(A2) U20.4(VSS) U59.3(GND)
VDDD33: R217.1
VDDL19: C126.1 C290.1 R255.2 U5.1(OE) U5.6(VCC) U59.6(VCC)
CALSTAT_FMC: J1.G28 ; port CALSTAT_FMC
CALTRIG_FMC: J1.G27 ; port CALTRIG_FMC
CSb_ADC_FMC: J1.H34 ; port CSb_ADC_FMC
CSb_LMK_FMC: J1.H35 ; port CSb_LMK_FMC
CSb_LMX_FMC: J1.H37 ; port CSb_LMX_FMC
DA0_FMC_N: J1.A11 ; port DA0_FMC_N
DA0_FMC_P: J1.A10 ; port DA0_FMC_P
DA1_FMC_N: J1.C7 ; port DA1_FMC_N
DA1_FMC_P: J1.C6 ; port DA1_FMC_P
DA2_FMC_N: J1.A7 ; port DA2_FMC_N
DA2_FMC_P: J1.A6 ; port DA2_FMC_P
DA3_FMC_N: J1.A3 ; port DA3_FMC_N
DA3_FMC_P: J1.A2 ; port DA3_FMC_P
DA4_FMC_N: J1.Z13 ; port DA4_FMC_N
DA4_FMC_P: J1.Z12 ; port DA4_FMC_P
DA5_FMC_N: J1.Y11 ; port DA5_FMC_N
DA5_FMC_P: J1.Y10 ; port DA5_FMC_P
DA6_FMC_N: J1.B9 ; port DA6_FMC_N
DA6_FMC_P: J1.B8 ; port DA6_FMC_P
DA7_FMC_N: J1.B5 ; port DA7_FMC_N
DA7_FMC_P: J1.B4 ; port DA7_FMC_P
DB0_FMC_N: J1.B12 ; port DB0_FMC_N
DB0_FMC_P: J1.B13 ; port DB0_FMC_P
DB1_FMC_N: J1.A14 ; port DB1_FMC_N
DB1_FMC_P: J1.A15 ; port DB1_FMC_P
DB2_FMC_N: J1.B16 ; port DB2_FMC_N
DB2_FMC_P: J1.B17 ; port DB2_FMC_P
DB3_FMC_N: J1.A18 ; port DB3_FMC_N
DB3_FMC_P: J1.A19 ; port DB3_FMC_P
DB4_FMC_N: J1.Y14 ; port DB4_FMC_N
DB4_FMC_P: J1.Y15 ; port DB4_FMC_P
DB5_FMC_N: J1.Z16 ; port DB5_FMC_N
DB5_FMC_P: J1.Z17 ; port DB5_FMC_P
DB6_FMC_N: J1.Y18 ; port DB6_FMC_N
DB6_FMC_P: J1.Y19 ; port DB6_FMC_P
DB7_FMC_N: J1.Y22 ; port DB7_FMC_N
DB7_FMC_P: J1.Y23 ; port DB7_FMC_P
FGPA_GBTCLK5_FMC_N: J1.Z21 ; port FGPA_GBTCLK5_FMC_N
FGPA_GBTCLK5_FMC_P: J1.Z20 ; port FGPA_GBTCLK5_FMC_P
FPGA_CLKA_FMC_N: J1.L25 ; port FPGA_CLKA_FMC_N
FPGA_CLKA_FMC_P: J1.L24 ; port FPGA_CLKA_FMC_P
FPGA_CLKB_FMC_N: J1.G7 ; port FPGA_CLKB_FMC_N
FPGA_CLKB_FMC_P: J1.G6 ; port FPGA_CLKB_FMC_P
FPGA_GBTCLK0_FMC_N: J1.D5 ; port FPGA_GBTCLK0_FMC_N
FPGA_GBTCLK0_FMC_P: J1.D4 ; port FPGA_GBTCLK0_FMC_P
FPGA_GBTCLK1_FMC_N: J1.B21 ; port FPGA_GBTCLK1_FMC_N
FPGA_GBTCLK1_FMC_P: J1.B20 ; port FPGA_GBTCLK1_FMC_P
FPGA_SYSREF_FMC_N: J1.G10 ; port FPGA_SYSREF_FMC_N
FPGA_SYSREF_FMC_P: J1.G9 ; port FPGA_SYSREF_FMC_P
GA0_FMC: J1.C34 R218.1 U20.1(A0)
GA1_FMC: J1.D35 R220.1 U20.2(A1)
HSPC-PRSNT-M2C-L: J1.Z1 R107.1
NCOA0_FMC: J1.H25 ; port NCOA0_FMC
NCOA1_FMC: J1.H26 ; port NCOA1_FMC
NCOB0_FMC: J1.H28 ; port NCOB0_FMC
NCOB1_FMC: J1.H29 ; port NCOB1_FMC
ORA0_FMC: J1.D26 ; port ORA0_FMC
ORA1_FMC: J1.D27 ; port ORA1_FMC
ORB0_FMC: J1.C26 ; port ORB0_FMC
ORB1_FMC: J1.C27 ; port ORB1_FMC
PD_FMC: J1.G30 ; port PD_FMC
PG-C2M: J1.D1 R103.1
PG-M2C: J1.F1 R103.2
PRSNT-M2C-L: J1.H2 R104.1
REF_SEL_FMC: J1.G12 ; port REF_SEL_FMC
SCL2_FMC: J1.G13 ; port SCL2_FMC
SCL_FMC: R807.1 ; port SCL_FMC
SCLK_FMC: J1.G31 ; port SCLK_FMC
SDA2_I_FMC: J1.G37 ; port SDA2_I_FMC
SDA2_O_FMC: J1.H38 ; port SDA2_O_FMC
SDA_FMC: R808.1 ; port SDA_FMC
SDI_FMC: J1.G33 ; port SDI_FMC
SDO_ADC_FMC: J1.G34 ; port SDO_ADC_FMC
SDO_LMKX_FMC: J1.G36 ; port SDO_LMKX_FMC
SYNCB_ADC: U59.4(Y) ; port SYNCB_ADC
SYNCB_I: J25.1 R255.1 U59.2(B)
SYNCB_O: J1.H32 J24.1 R254.2
TDI_FMC: J1.D30 R105.2
TDO_FMC: J1.D31 R105.1
NetC92_1: C92.1 R215.2 R217.2 U20.8(VCC)
NetJ1_C30: J1.C30 R807.2 U20.6(SCL)
NetJ1_C31: J1.C31 R808.2 U20.5(SDA)
NetJ1_H31: J1.H31 U5.2(A) U59.1(A)
NetR254_1: R254.1 U5.4(Y)

Not connected (* = marked no-connect by the designer): J1 A22* A23* A26* A27* A30* A31* A34* A35* A38* A39* B1* B24* B25* B28* B29* B32* B33* B36* B37* B40* C2* C3* C10* C11* C14* C15* C16* C18* C19* C22* C23* C35* C37* C39* D8* D9* D11* D12* D14* D15* D16* D17* D18* D20* D21* D23* D24* D29 D33 D34 D36* D38* D40* E2* E3* E6* E7* E9* E10* E12* E13* E15* E16* E17* E18* E19* E21* E22* E24* E25* E27* E28* E30* E31* E33* E34* E36* E37* E39* F4* F5* F7* F8* F10* F11* F13* F14* F15* F16* F17* F18* F19* F20* F22* F23* F25* F26* F28* F29* F31* F32* F34 F35 F37 F38* F40* G2* G3* G15* G16* G17* G18* G19* G21* G22* G24* G25* G39* H1* H4* H5* H7* H8* H10* H11* H13* H14* H15* H16* H17* H19* H20* H22* H23* H40* J2* J3* J5* J6* J7* J9* J10* J12* J13* J15* J16* J17* J18* J19* J21 J22 J24* J25* J27* J28* J30* J31* J33* J34* J36* J37* J39* K1* K4* K5* K7* K8* K10* K11* K12* K13* K14* K15* K16* K17* K19* K20* K22* K23* K25* K26* K28* K29* K31* K32* K34* K35* K37* K38* K40* L1* L4* L5* L8* L9* L10* L12* L13* L15* L16* L17* L19* L20* L21* L28* L29* L32* L33* L36* L37* L40* M2* M3* M6* M7* M10* M11* M14* M15* M18* M19* M22* M23* M26* M27* M30* M31* M34* M35* M38* M39* Y2* Y3* Y6* Y7* Y26* Y27* Y30* Y31* Y34* Y35* Y38* Y39* Z4* Z5* Z8* Z9* Z24* Z25* Z28* Z29* Z32* Z33* Z36* Z37* Z40*; U5 5(NC)*; U20 7(NC)*; U59 5(NC)*

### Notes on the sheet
- Not on J57

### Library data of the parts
C92 C126 C290 = CMP-0064970-1: as C96 on sheet Clocks2_RevE2
J1 = CMP-0055662-1: Terminal Array, 1.27mm, 40x14, Gold, SMT; Manufacturer: Samtec; CNHeader: FALSE; Shrouded: Y; Gender: Male; Row_Count: 14; RowSpacing_mm: 1.27
J24 J25 = CMP-0054947-1: as J13 on sheet Clocks2_RevE2
R103 R105 R215 R217 R218 R220 R807 R808 = CMP-0027008-4: as R240 on sheet Clocks2_RevE2
R104 R107 = CMP-0028070-1: RES, 100, 1%, 0.05 W, 0201; Manufacturer: Yageo America; Power_W: 50mW; TempCo: 200 ppm/C; Value_Code: 100R; U/M: EA; Value: 100; EIA_Code: E96; SizeX_mm: 0.6; SizeY_mm: 0.3; SizeZ_mm: 0.26; Value2: 0.05W; SizeArea_mm2: 0.18; AEC Qualified: N; VDC_V: 25V; AEC Category: Q200
R254 = CMP-0028028-1: RES, 49.9, 1%, 0.05 W, 0201; Manufacturer: Yageo America; Power_W: 50mW; TempCo: 200 ppm/C; Value_Code: 49R9; U/M: EA; Value: 49.9; EIA_Code: E96; SizeX_mm: 0.6; SizeY_mm: 0.3; SizeZ_mm: 0.26; Value2: 0.05W; SizeArea_mm2: 0.18; CompType: Resistor; AEC Qualified: N; VDC_V: 25V; AEC Category: Q200
R255 = CMP-0027945-1: RES, 10.0 k, 1%, 0.05 W, 0201; Manufacturer: Yageo America; Power_W: 50mW; TempCo: 200 ppm/C; Value_Code: 10k0; U/M: EA; Value: 10.0k; EIA_Code: E96; Res_ohm: 10k; SizeX_mm: 0.6; SizeY_mm: 0.3; SizeZ_mm: 0.26; Value2: 0.05W; SizeArea_mm2: 0.18; CompType: Resistor; AEC Qualified: N; VDC_V: 25V; AEC Category: Q200
U5 = CMP-0051432-4: Low-Power Single Bus Buffer Gate with 3-State Output, DRY0006A (USON-6); Manufacturer: Texas Instruments; Output Type: CMOS; Bits(#): 1; Technology Family: AUP; Schmitt Trigger: No; 3-State Output: Yes; VCC(Max)(V): 3.6; Rating: Catalog; Output Drive (IOL/IOH)(Max)(mA): 20/-20; ICC @ Nom Voltage(Max)(mA): 0.0009; VCC(Min)(V): 0.8; F @ Nom Voltage(Max)(Mhz): 100; Logic: True; Voltage(Nom)(V): 0.8,1.2,1.5,1.8,2.5,3.3; tpd @ Nom Voltage(Max)(ns): 29,18.7,12.5,10.1,7.2,6; AEC Category: Q200; AEC Qualified: N; CompType: IC; SizeAreaWB_mm2: 4.9; SizeArea_mm2: 1.45; SizeX_mm: 1.0; SizeZ_mm: 0.6
U20 = CMP-0005258-2: 64K I2C Smart Serial EEPROM, SOIC-8; Manufacturer: Microchip
U59 = CMP-0051421-4: Low-Power Single 2-Input Positive-AND Gate, DRY0006A (USON-6); Manufacturer: Texas Instruments; Output Type: CMOS; Bits(#): 1; Technology Family: AUP; Schmitt Trigger: No; VCC(Max)(V): 3.6; Gate Type: AND; Rating: Catalog; Output Drive (IOL/IOH)(Max)(mA): 20/-20; ICC @ Nom Voltage(Max)(mA): 0.0009; VCC(Min)(V): 0.8; F @ Nom Voltage(Max)(Mhz): 100; Logic: True; Voltage(Nom)(V): 0.8,1.2,1.5,1.8,2.5,3.3; tpd @ Nom Voltage(Max)(ns): 32.8,20.9,14.2,11,7.6,6.2; AEC Category: Q200; AEC Qualified: N; CompType: IC; SizeAreaWB_mm2: 4.9; SizeArea_mm2: 1.45; SizeX_mm: 1.0; SizeZ_mm: 0.6

## Sheet GPIO_RevE2.SchDoc: EVM GPIO
size 431 x 279 mm; Date: Not shown in title block; ApprovedBy: Not shown in title block; CheckedBy: Not shown in title block; Author: Not shown in title block; CompanyName: Not shown in title block; DrawnBy: DWG; Engineer: DWG; Organization: Not shown in title block; Address1: Not shown in title block; Address2: Not shown in title block; Address3: Not shown in title block; Address4: Not shown in title block; DocumentNumber: 9; Revision: Use project parameter SCH_Rev; SheetNumber: 9; SheetTotal: 15; PageSetup: Record=PageOptions¦CenterHorizontal=True¦CenterVertical=True¦PrintScale=1.00¦XCorrection=1.00¦YCorrection=1.00¦PrintKind=0¦BorderSize=5000000¦LeftOffset=0¦BottomOffset=0¦Orientation=2¦PaperLength=1000¦PaperWidth=1000¦Scale=100¦PaperSource=15¦PrintQuality=600¦MediaType=1¦DitherType=10¦PaperKind=Letter¦PrintScaleMode=1
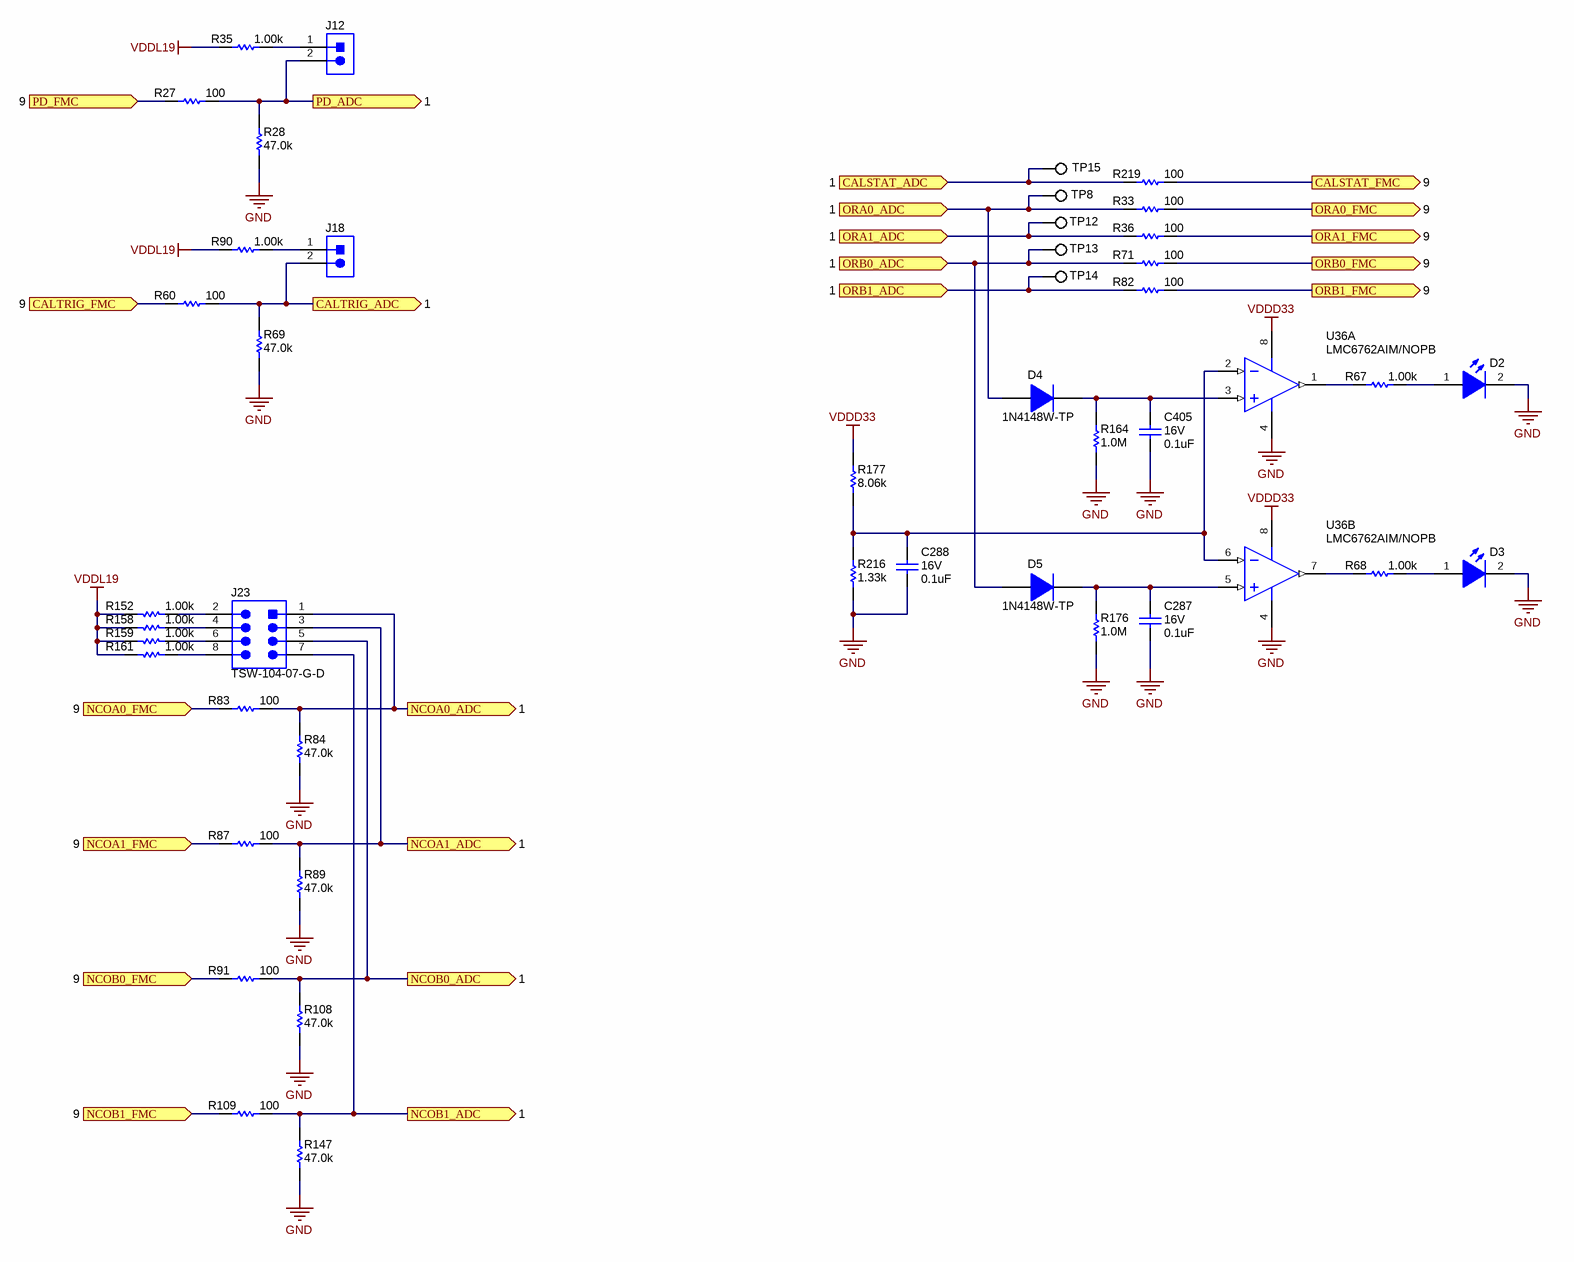
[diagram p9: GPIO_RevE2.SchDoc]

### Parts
C287  VDC_V: 16V  ValueDisplayed: 0.1uF  [0201]  (hidden comment: GRM033Z71C104KE14D)
C288  VDC_V: 16V  ValueDisplayed: 0.1uF  [0201]  (hidden comment: GRM033Z71C104KE14D)
C405  VDC_V: 16V  ValueDisplayed: 0.1uF  [0201]  (hidden comment: GRM033Z71C104KE14D)
D2  LTST-C170KRKT  [LED_LTST-C170_Red]  (value not drawn)
D3  LTST-C170KRKT  [LED_LTST-C170_Red]  (value not drawn)
D4  1N4148W-TP  [SOD-123]
D5  1N4148W-TP  [SOD-123]
J12  5-146261-1  [CONN_5-146261-1]  (value not drawn)
J18  5-146261-1  [CONN_5-146261-1]  (value not drawn)
J23  TSW-104-07-G-D  [TSW-104-07-G-D]
R27  ValueDisplayed: 100  [0201L]  (hidden comment: RC0201FS-7D100RL)
R28  ValueDisplayed: 47.0k  [0201L]  (hidden comment: RC0201FR-0747KL)
R33  ValueDisplayed: 100  [0201L]  (hidden comment: RC0201FS-7D100RL)
R35  ValueDisplayed: 1.00k  [0201L]  (hidden comment: RC0201FS-7D1KL)
R36  ValueDisplayed: 100  [0201L]  (hidden comment: RC0201FS-7D100RL)
R60  ValueDisplayed: 100  [0201L]  (hidden comment: RC0201FS-7D100RL)
R67  ValueDisplayed: 1.00k  [0201]  (hidden comment: RC0201FS-7D1KL)
R68  ValueDisplayed: 1.00k  [0201]  (hidden comment: RC0201FS-7D1KL)
R69  ValueDisplayed: 47.0k  [0201L]  (hidden comment: RC0201FR-0747KL)
R71  ValueDisplayed: 100  [0201L]  (hidden comment: RC0201FS-7D100RL)
R82  ValueDisplayed: 100  [0201L]  (hidden comment: RC0201FS-7D100RL)
R83  ValueDisplayed: 100  [0201L]  (hidden comment: RC0201FS-7D100RL)
R84  ValueDisplayed: 47.0k  [0201L]  (hidden comment: RC0201FR-0747KL)
R87  ValueDisplayed: 100  [0201L]  (hidden comment: RC0201FS-7D100RL)
R89  ValueDisplayed: 47.0k  [0201L]  (hidden comment: RC0201FR-0747KL)
R90  ValueDisplayed: 1.00k  [0201L]  (hidden comment: RC0201FS-7D1KL)
R91  ValueDisplayed: 100  [0201L]  (hidden comment: RC0201FS-7D100RL)
R108  ValueDisplayed: 47.0k  [0201L]  (hidden comment: RC0201FR-0747KL)
R109  ValueDisplayed: 100  [0201L]  (hidden comment: RC0201FS-7D100RL)
R147  ValueDisplayed: 47.0k  [0201L]  (hidden comment: RC0201FR-0747KL)
R152  ValueDisplayed: 1.00k  [0201L]  (hidden comment: RC0201FS-7D1KL)
R158  ValueDisplayed: 1.00k  [0201L]  (hidden comment: RC0201FS-7D1KL)
R159  ValueDisplayed: 1.00k  [0201L]  (hidden comment: RC0201FS-7D1KL)
R161  ValueDisplayed: 1.00k  [0201L]  (hidden comment: RC0201FS-7D1KL)
R164  ValueDisplayed: 1.0M  [0201]  (hidden comment: RC0201JR-071ML)
R176  ValueDisplayed: 1.0M  [0201]  (hidden comment: RC0201JR-071ML)
R177  ValueDisplayed: 8.06k  [0201]  (hidden comment: RC0201FS-7D8K06L)
R216  ValueDisplayed: 1.33k  [0201]  (hidden comment: RC0201FR-071K33L)
R219  ValueDisplayed: 100  [0201L]  (hidden comment: RC0201FS-7D100RL)
TP8  5002  [Keystone5002]  (value not drawn)
TP12  5002  [Keystone5002]  (value not drawn)
TP13  5002  [Keystone5002]  (value not drawn)
TP14  5002  [Keystone5002]  (value not drawn)
TP15  5002  [Keystone5002]  (value not drawn)
U36  LMC6762AIM/NOPB  [D0008A_N]  (parts A,B of 2)

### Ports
CALSTAT_ADC (in, see 1), CALSTAT_FMC (out, see 9), CALTRIG_ADC (out, see 1), CALTRIG_FMC (in, see 9), NCOA0_ADC (out, see 1), NCOA0_FMC (in, see 9), NCOA1_ADC (out, see 1), NCOA1_FMC (in, see 9), NCOB0_ADC (out, see 1), NCOB0_FMC (in, see 9), NCOB1_ADC (out, see 1), NCOB1_FMC (in, see 9), ORA0_ADC (in, see 1), ORA0_FMC (out, see 9), ORA1_ADC (in, see 1), ORA1_FMC (out, see 9), ORB0_ADC (in, see 1), ORB0_FMC (out, see 9), ORB1_ADC (in, see 1), ORB1_FMC (out, see 9), PD_ADC (out, see 1), PD_FMC (in, see 9)

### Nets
GND: C287.1 C288.1 C405.1 D2.2(K) D3.2(K) R28.1 R69.1 R84.1 R89.1 R108.1 R147.1 R164.1 R176.1 R216.1 U36.4(V-)
VDDD33: R177.2 U36.8(V+)
VDDL19: R35.1 R90.1 R152.2 R158.2 R159.2 R161.2
CALSTAT_ADC: R219.2 TP15.1 ; port CALSTAT_ADC
CALSTAT_FMC: R219.1 ; port CALSTAT_FMC
CALTRIG_ADC: J18.2 R60.1 R69.2 ; port CALTRIG_ADC
CALTRIG_FMC: R60.2 ; port CALTRIG_FMC
NCOA0_ADC: J23.1 R83.1 R84.2 ; port NCOA0_ADC
NCOA0_FMC: R83.2 ; port NCOA0_FMC
NCOA1_ADC: J23.3 R87.1 R89.2 ; port NCOA1_ADC
NCOA1_FMC: R87.2 ; port NCOA1_FMC
NCOB0_ADC: J23.5 R91.1 R108.2 ; port NCOB0_ADC
NCOB0_FMC: R91.2 ; port NCOB0_FMC
NCOB1_ADC: J23.7 R109.1 R147.2 ; port NCOB1_ADC
NCOB1_FMC: R109.2 ; port NCOB1_FMC
ORA0_ADC: D4.2(A) R33.2 TP8.1 ; port ORA0_ADC
ORA0_FMC: R33.1 ; port ORA0_FMC
ORA1_ADC: R36.2 TP12.1 ; port ORA1_ADC
ORA1_FMC: R36.1 ; port ORA1_FMC
ORB0_ADC: D5.2(A) R71.2 TP13.1 ; port ORB0_ADC
ORB0_FMC: R71.1 ; port ORB0_FMC
ORB1_ADC: R82.2 TP14.1 ; port ORB1_ADC
ORB1_FMC: R82.1 ; port ORB1_FMC
PD_ADC: J12.2 R27.1 R28.2 ; port PD_ADC
PD_FMC: R27.2 ; port PD_FMC
NetC287_2: C287.2 D5.1(K) R176.2 U36.5(INB+)
NetC288_2: C288.2 R177.1 R216.2 U36.2(INA-) U36.6(INB-)
NetC405_2: C405.2 D4.1(K) R164.2 U36.3(INA+)
NetD2_1: D2.1(A) R67.2
NetD3_1: D3.1(A) R68.2
NetJ12_1: J12.1 R35.2
NetJ18_1: J18.1 R90.2
NetJ23_2: J23.2 R152.1
NetJ23_4: J23.4 R158.1
NetJ23_6: J23.6 R159.1
NetJ23_8: J23.8 R161.1
NetR67_1: R67.1 U36.1(OUTA)
NetR68_1: R68.1 U36.7(OUTB)

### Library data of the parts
C287 C288 C405 = CMP-0064970-1: CAP, CERM, 0.1 uF, 16 V,+/- 10%, X7R, 0201; Manufacturer: MuRata; TaMin_C: -55°C; Polarized: N; SizeAreaWB_mm2: 2.08; Value1: Unknown; U/M: EA; Value: 0.1uF; TaMax_C: 125°C; SizeZ_mm: 0.26; SizeX_mm: 0.6; SizeY_mm: 0.3; SizeArea_mm2: 0.18; Cap_F: 100nF; AEC Category: Q200
D2 D3 = CMP-0002829-3: LED, Red, SMD; Manufacturer: Lite-On; Io_A: 20mA; SizeAreaWB_mm2: 6.75; Value1: W; SizeZ_mm: 1.2; SizeX_mm: 2; SizeY_mm: 1.25; Vf_V: 2V; SizeArea_mm2: 2.5; Type: AlInGaP
D4 D5 = CMP-0076974-2: Diode, Switching, 100 V, 0.15 A, SOD-123; Manufacturer: Micro Commercial Components; SizeAreaWB_mm2: 13.095; Vr_V: 100V; SizeArea_mm2: 6.545; TJmax_C: 150°C; AEC Category: Q101; Value: 100V; SizeZ_mm: 1.35; Green_REACh: Incomplete; Io_A: 1.5dA; Vf_V: 1.25V; SizeY_mm: 1.7; Green_Lifecycle: Not Set; Value1: 0.15A; SizeX_mm: 3.85
J12 J18 = CMP-0054947-1: as J13 on sheet Clocks2_RevE2
J23 = CMP-0075408-2: Header, 100mil, 4x2, Gold, TH; Manufacturer: Samtec; Pitch_mm: 2.54; Cert_VDE: N; Gender: Male; Cert_CSA: Y; Voltage_V: 550V; Green_REACh: Passed; Current_A: 6.3A; Green_Lifecycle: Active; Row_Count: 2
R27 R60 R83 R87 R91 R109 = CMP-0028070-1: as R239 on sheet Clocks2_RevE2
R28 R69 R84 R89 R108 R147 = CMP-0027723-1: RES, 47.0 k, 1%, 0.05 W, 0201; Manufacturer: Yageo America; Power_W: 50mW; TempCo: 200 ppm/C; Value_Code: 47k0; U/M: EA; Value: 47.0k; Res_ohm: 47k; SizeX_mm: 0.6; SizeY_mm: 0.3; SizeZ_mm: 0.26; Value2: 0.05W; SizeArea_mm2: 0.18; CompType: Resistor; AEC Qualified: N; VDC_V: 25V; AEC Category: Q200
R33 R36 R71 R82 R219 = CMP-0028070-1: as R104 on sheet FMC_RevE2
R35 R67 R68 R90 R152 R158 R159 R161 = CMP-0028084-1: RES, 1.00 k, 1%, 0.05 W, 0201; Manufacturer: Yageo America; Power_W: 50mW; TempCo: 200 ppm/C; Value_Code: 1k00; U/M: EA; Value: 1.00k; EIA_Code: E96; Res_ohm: 1k; SizeX_mm: 0.6; SizeY_mm: 0.3; SizeZ_mm: 0.26; Value2: 0.05W; SizeArea_mm2: 0.18; AEC Qualified: N; VDC_V: 25V; AEC Category: Q200
R164 R176 = CMP-0027059-1: RES, 1.0 M, 5%, 0.05 W, 0201; Manufacturer: Yageo America; Power_W: 50mW; TempCo: 200 ppm/C; Value_Code: 1M00; U/M: EA; Value: 1.0Meg; EIA_Code: E24; Res_ohm: 1M; SizeX_mm: 0.6; SizeY_mm: 0.3; SizeZ_mm: 0.26; Value2: 0.05W; SizeArea_mm2: 0.18; AEC Qualified: N; VDC_V: 25V; AEC Category: Q200
R177 = CMP-0028120-1: RES, 8.06 k, 1%, 0.05 W, 0201; Manufacturer: Yageo America; Power_W: 50mW; TempCo: 200 ppm/C; Value_Code: 8k06; U/M: EA; Value: 8.06k; EIA_Code: E96; SizeX_mm: 0.6; SizeY_mm: 0.3; SizeZ_mm: 0.26; Value2: 0.05W; SizeArea_mm2: 0.18; AEC Qualified: N; VDC_V: 25V; AEC Category: Q200
R216 = CMP-0027433-1: RES, 1.33 k, 1%, 0.05 W, 0201; Manufacturer: Yageo America; Power_W: 50mW; TempCo: 200 ppm/C; Value_Code: 1k33; U/M: EA; Value: 1.33k; EIA_Code: E96; SizeX_mm: 0.6; SizeY_mm: 0.3; SizeZ_mm: 0.26; Value2: 0.05W; SizeArea_mm2: 0.18; AEC Qualified: N; VDC_V: 25V; AEC Category: Q200
TP8 TP12-TP15 = CMP-0055139-1: Test Point, Miniature, White, TH; Manufacturer: Keystone; CNHeader: FALSE; Green_Lifecycle: Active; Green_REACh: Passed; ContactFinish: Silver; CT: TRUE
U36 = CMP-0068362-2: Dual Micro-Power Rail-to-Rail Input CMOS Comparator with Push-Pull Output, 8-pin Narrow SOIC, Pb-Free; Manufacturer: Texas Instruments; CompType: IC; AEC Category: Q200; AEC Qualified: N; SizeAreaWB_mm2: 56.58; SizeArea_mm2: 30.38; SizeX_mm: 4.9; SizeY_mm: 6.2; SizeZ_mm: 1.75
